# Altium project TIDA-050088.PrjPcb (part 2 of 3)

## Sheet TIDA-050088_LDOs.SchDoc
size 558 x 431 mm; Date: Not shown in title block; ApprovedBy: Not shown in title block; CheckedBy: Not shown in title block; Author: Not shown in title block; CompanyName: Not shown in title block; Engineer: Not shown in title block; Organization: Not shown in title block; Address1: Not shown in title block; Address2: Not shown in title block; Address3: Not shown in title block; Address4: Not shown in title block; DocumentNumber: 2; Revision: Use project parameter SCH_Rev; SheetNumber: 4; SheetTotal: 7; PageSetup: Record=PageOptions¦CenterHorizontal=True¦CenterVertical=True¦PrintScale=1.00¦XCorrection=1.00¦YCorrection=1.00¦PrintKind=0¦BorderSize=5000000¦LeftOffset=0¦BottomOffset=0¦Orientation=2¦PaperLength=1000¦PaperWidth=1000¦Scale=100¦PaperSource=15¦PrintQuality=600¦MediaType=1¦DitherType=10¦PaperKind=Letter¦PrintScaleMode=1
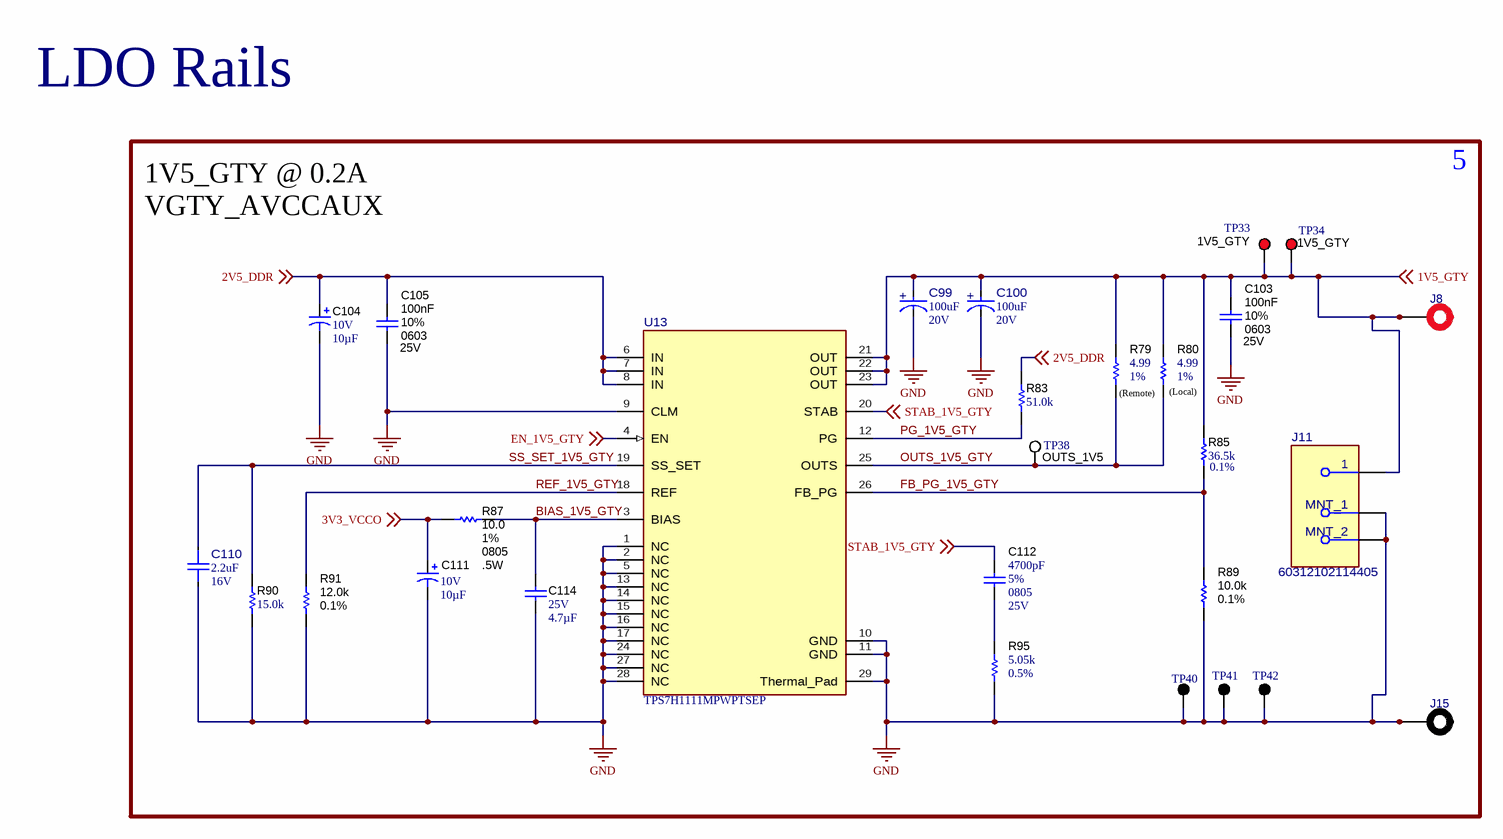
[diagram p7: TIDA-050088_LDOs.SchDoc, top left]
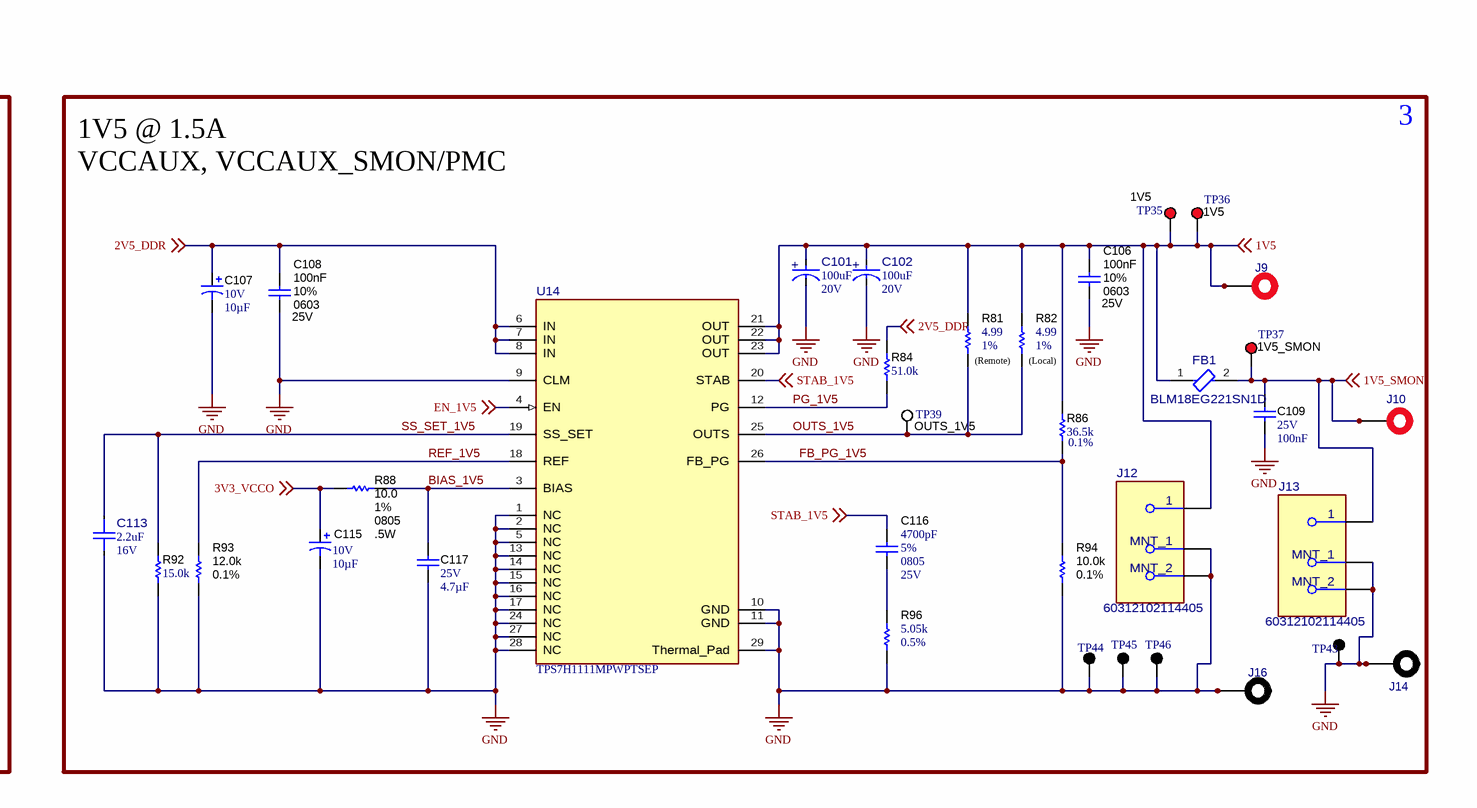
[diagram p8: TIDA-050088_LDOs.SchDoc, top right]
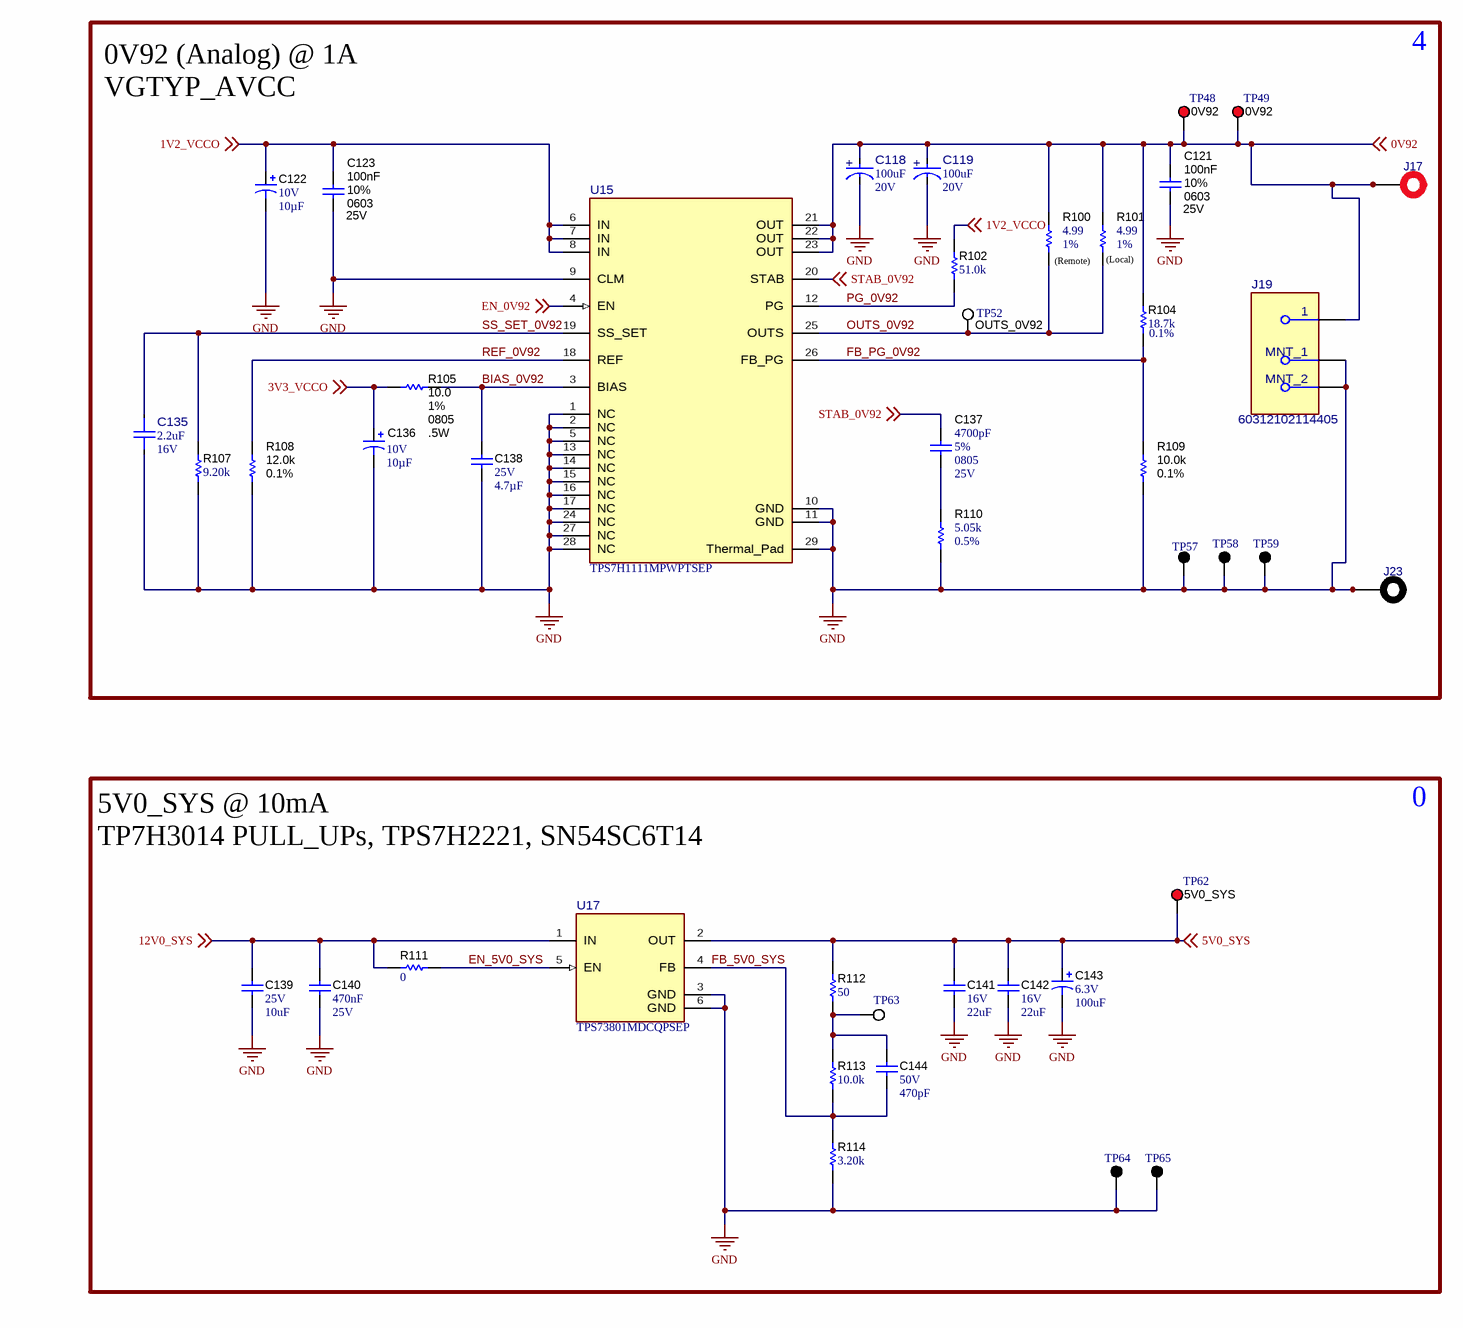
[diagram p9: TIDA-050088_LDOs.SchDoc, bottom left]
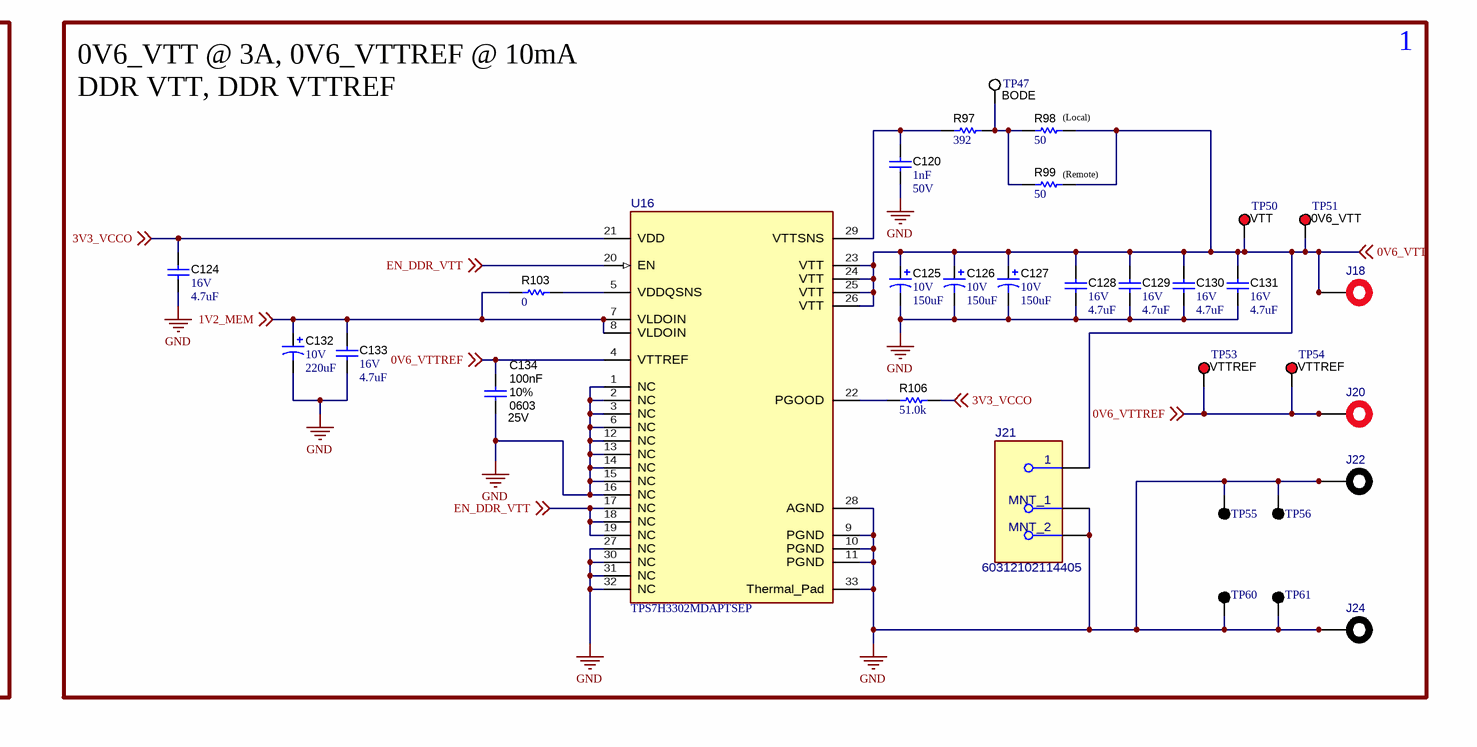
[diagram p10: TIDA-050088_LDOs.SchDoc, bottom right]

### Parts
C99  ValueDisplayed: 100uF  VDC_V: 20V  [FP-TRME107K020R0035_2917-MFG]  (hidden comment: TRME107K020R0035)
C100  ValueDisplayed: 100uF  VDC_V: 20V  [FP-TRME107K020R0035_2917-MFG]  (hidden comment: TRME107K020R0035)
C101  ValueDisplayed: 100uF  VDC_V: 20V  [FP-TRME107K020R0035_2917-MFG]  (hidden comment: TRME107K020R0035)
C102  ValueDisplayed: 100uF  VDC_V: 20V  [FP-TRME107K020R0035_2917-MFG]  (hidden comment: TRME107K020R0035)
C103  Tolerance_%: 10%  Cap_F: 100nF  VDC_V: 25V  [0603]  (hidden comment: C1608X7R1E104K080AA)
C104  VDC_V: 10V  ValueDisplayed: 10µF  [3216-18]  (hidden comment: T520A106M010ATE080)
C105  Tolerance_%: 10%  Cap_F: 100nF  VDC_V: 25V  [0603]  (hidden comment: 885012206071)
C106  Tolerance_%: 10%  Cap_F: 100nF  VDC_V: 25V  [0603]  (hidden comment: C1608X7R1E104K080AA)
C107  VDC_V: 10V  ValueDisplayed: 10µF  [3216-18]  (hidden comment: T520A106M010ATE080)
C108  Tolerance_%: 10%  Cap_F: 100nF  VDC_V: 25V  [0603]  (hidden comment: 885012206071)
C109  VDC_V: 25V  Cap_F: 100nF  [0603]  (hidden comment: GCM188R71E104KA57D)
C110  ValueDisplayed: 2.2uF  VDC_V: 16V  [FP-C1206C225K4RAC7800_1206-MFG]  (hidden comment: C1206C225K4RAC7800)
C111  VDC_V: 10V  ValueDisplayed: 10µF  [3216-18]  (hidden comment: T520A106M010ATE080)
C112  PackageReference: 0805  Tolerance_%: 5%  VDC_V: 25V  ValueDisplayed: 4700pF  [0805_HV]  (hidden comment: 08053A472JAT2A)
C113  ValueDisplayed: 2.2uF  VDC_V: 16V  [FP-C1206C225K4RAC7800_1206-MFG]  (hidden comment: C1206C225K4RAC7800)
C114  VDC_V: 25V  ValueDisplayed: 4.7µF  [1206_180]  (hidden comment: 12063C475KAT2A)
C115  VDC_V: 10V  ValueDisplayed: 10µF  [3216-18]  (hidden comment: T520A106M010ATE080)
C116  PackageReference: 0805  Tolerance_%: 5%  VDC_V: 25V  ValueDisplayed: 4700pF  [0805_HV]  (hidden comment: 08053A472JAT2A)
C117  VDC_V: 25V  ValueDisplayed: 4.7µF  [1206_180]  (hidden comment: 12063C475KAT2A)
C118  ValueDisplayed: 100uF  VDC_V: 20V  [FP-TRME107K020R0035_2917-MFG]  (hidden comment: TRME107K020R0035)
C119  ValueDisplayed: 100uF  VDC_V: 20V  [FP-TRME107K020R0035_2917-MFG]  (hidden comment: TRME107K020R0035)
C120  Cap_F: 1nF  VDC_V: 50V  [0603]  (hidden comment: C0603X102K5RACTU)
C121  Tolerance_%: 10%  Cap_F: 100nF  VDC_V: 25V  [0603]  (hidden comment: C1608X7R1E104K080AA)
C122  VDC_V: 10V  ValueDisplayed: 10µF  [3216-18]  (hidden comment: T520A106M010ATE080)
C123  Tolerance_%: 10%  Cap_F: 100nF  VDC_V: 25V  [0603]  (hidden comment: 885012206071)
C124  VDC_V: 16V  ValueDisplayed: 4.7uF  [1206_180]  (hidden comment: GCM31CR71C475KA37L)
C125  VDC_V: 10V  ValueDisplayed: 150uF  [7343-31]  (hidden comment: T530D157M010ATE005)
C126  VDC_V: 10V  ValueDisplayed: 150uF  [7343-31]  (hidden comment: T530D157M010ATE005)
C127  VDC_V: 10V  ValueDisplayed: 150uF  [7343-31]  (hidden comment: T530D157M010ATE005)
C128  VDC_V: 16V  ValueDisplayed: 4.7uF  [1206_180]  (hidden comment: GCM31CR71C475KA37L)
C129  VDC_V: 16V  ValueDisplayed: 4.7uF  [1206_180]  (hidden comment: GCM31CR71C475KA37L)
C130  VDC_V: 16V  ValueDisplayed: 4.7uF  [1206_180]  (hidden comment: GCM31CR71C475KA37L)
C131  VDC_V: 16V  ValueDisplayed: 4.7uF  [1206_180]  (hidden comment: GCM31CR71C475KA37L)
C132  VDC_V: 10V  ValueDisplayed: 220uF  [7343-31]  (hidden comment: T520D227M010ATE018)
C133  VDC_V: 16V  ValueDisplayed: 4.7uF  [1206_180]  (hidden comment: GCM31CR71C475KA37L)
C134  Tolerance_%: 10%  Cap_F: 100nF  VDC_V: 25V  [0603]  (hidden comment: C1608X7R1E104K080AA)
C135  ValueDisplayed: 2.2uF  VDC_V: 16V  [FP-C1206C225K4RAC7800_1206-MFG]  (hidden comment: C1206C225K4RAC7800)
C136  VDC_V: 10V  ValueDisplayed: 10µF  [3216-18]  (hidden comment: T520A106M010ATE080)
C137  PackageReference: 0805  Tolerance_%: 5%  VDC_V: 25V  ValueDisplayed: 4700pF  [0805_HV]  (hidden comment: 08053A472JAT2A)
C138  VDC_V: 25V  ValueDisplayed: 4.7µF  [1206_180]  (hidden comment: 12063C475KAT2A)
C139  VDC_V: 25V  ValueDisplayed: 10uF  [1210_220]  (hidden comment: 885012209028)
C140  Cap_F: 470nF  VDC_V: 25V  [0805_HV]  (hidden comment: CL21B474KAFNNNG)
C141  VDC_V: 16V  ValueDisplayed: 22uF  [1210_280]  (hidden comment: CGA6P1X7R1C226M250AC)
C142  VDC_V: 16V  ValueDisplayed: 22uF  [1210_280]  (hidden comment: CGA6P1X7R1C226M250AC)
C143  VDC_V: 6.3V  ValueDisplayed: 100uF  [3528-21]  (hidden comment: T520B107M006ATE015)
C144  VDC_V: 50V  ValueDisplayed: 470pF  [0603]  (hidden comment: GCM1885C1H471JA16D)
FB1  BLM18EG221SN1D  [FP-BLM18EG221SN1D_0603-MFG]
J8  571-0500  [571-0500]  (value not drawn)
J9  571-0500  [571-0500]  (value not drawn)
J10  571-0500  [571-0500]  (value not drawn)
J11  60312102114405  [FP-60312102114405_CONN_SMA-MFG]
J12  60312102114405  [FP-60312102114405_CONN_SMA-MFG]
J13  60312102114405  [FP-60312102114405_CONN_SMA-MFG]
J14  571-0100  [571-0100]  (value not drawn)
J15  571-0100  [571-0100]  (value not drawn)
J16  571-0100  [571-0100]  (value not drawn)
J17  571-0500  [571-0500]  (value not drawn)
J18  571-0500  [571-0500]  (value not drawn)
J19  60312102114405  [FP-60312102114405_CONN_SMA-MFG]
J20  571-0500  [571-0500]  (value not drawn)
J21  60312102114405  [FP-60312102114405_CONN_SMA-MFG]
J22  571-0100  [571-0100]  (value not drawn)
J23  571-0100  [571-0100]  (value not drawn)
J24  571-0100  [571-0100]  (value not drawn)
R79  Value1: 1%  ValueDisplayed: 4.99  [0603]  (hidden comment: RC0603FR-074R99L)
R80  Value1: 1%  ValueDisplayed: 4.99  [0603]  (hidden comment: RC0603FR-074R99L)
R81  Value1: 1%  ValueDisplayed: 4.99  [0603]  (hidden comment: RC0603FR-074R99L)
R82  Value1: 1%  ValueDisplayed: 4.99  [0603]  (hidden comment: RC0603FR-074R99L)
R83  ValueDisplayed: 51.0k  [0603]  (hidden comment: RC0603FR-0751KL)
R84  ValueDisplayed: 51.0k  [0603]  (hidden comment: RC0603FR-0751KL)
R85  Value1: 0.1%  ValueDisplayed: 36.5k  [0603]  (hidden comment: ERA-3AEB3652V)
R86  Value1: 0.1%  ValueDisplayed: 36.5k  [0603]  (hidden comment: ERA-3AEB3652V)
R87  Value1: 1%  PackageReference: 0805  Value2: .5W  ValueDisplayed: 10.0  [0805_HV]  (hidden comment: ERJ-P6WF10R0V)
R88  Value1: 1%  PackageReference: 0805  Value2: .5W  ValueDisplayed: 10.0  [0805_HV]  (hidden comment: ERJ-P6WF10R0V)
R89  Tolerance_%: 0.1%  ValueDisplayed: 10.0k  [0603]  (hidden comment: RT0603BRD0710KL)
R90  ValueDisplayed: 15.0k  [0603]  (hidden comment: RG1608P-153-B-T5)
R91  Value1: 0.1%  ValueDisplayed: 12.0k  [0603]  (hidden comment: RT0603BRD0712KL)
R92  ValueDisplayed: 15.0k  [0603]  (hidden comment: RG1608P-153-B-T5)
R93  Value1: 0.1%  ValueDisplayed: 12.0k  [0603]  (hidden comment: RT0603BRD0712KL)
R94  Tolerance_%: 0.1%  ValueDisplayed: 10.0k  [0603]  (hidden comment: RT0603BRD0710KL)
R95  Value1: 0.5%  ValueDisplayed: 5.05k  [0603]  (hidden comment: RT0603DRE075K05L)
R96  Value1: 0.5%  ValueDisplayed: 5.05k  [0603]  (hidden comment: RT0603DRE075K05L)
R97  ValueDisplayed: 392  [0603]  (hidden comment: RT0603BRD07392RL)
R98  ValueDisplayed: 50  [0603]  (hidden comment: FC0603E50R0BTBST1)
R99  ValueDisplayed: 50  [0603]  (hidden comment: FC0603E50R0BTBST1)
R100  Value1: 1%  ValueDisplayed: 4.99  [0603]  (hidden comment: RC0603FR-074R99L)
R101  Value1: 1%  ValueDisplayed: 4.99  [0603]  (hidden comment: RC0603FR-074R99L)
R102  ValueDisplayed: 51.0k  [0603]  (hidden comment: RC0603FR-0751KL)
R103  ValueDisplayed: 0  [0603]  (hidden comment: RCS06030000Z0EA)
R104  Value1: 0.1%  ValueDisplayed: 18.7k  [0603]  (hidden comment: ERA-3AEB1872V)
R105  Value1: 1%  PackageReference: 0805  Value2: .5W  ValueDisplayed: 10.0  [0805_HV]  (hidden comment: ERJ-P6WF10R0V)
R106  ValueDisplayed: 51.0k  [0603]  (hidden comment: RC0603FR-0751KL)
R107  ValueDisplayed: 9.20k  [0603]  (hidden comment: RT0603BRD079K2L)
R108  Value1: 0.1%  ValueDisplayed: 12.0k  [0603]  (hidden comment: RT0603BRD0712KL)
R109  Tolerance_%: 0.1%  ValueDisplayed: 10.0k  [0603]  (hidden comment: RT0603BRD0710KL)
R110  Value1: 0.5%  ValueDisplayed: 5.05k  [0603]  (hidden comment: RT0603DRE075K05L)
R111  ValueDisplayed: 0  [0603]  (hidden comment: RCS06030000Z0EA)
R112  ValueDisplayed: 50  [0603]  (hidden comment: FC0603E50R0BTBST1)
R113  ValueDisplayed: 10.0k  [0603]  (hidden comment: PHT0603Y1002BGT200)
R114  ValueDisplayed: 3.20k  [0603]  (hidden comment: RT0603BRD073K2L)
TP33  1V5_GTY  [Keystone5010]
TP34  1V5_GTY  [Keystone5010]
TP35  1V5  [Keystone5010]
TP36  1V5  [Keystone5010]
TP37  1V5_SMON  [Keystone5010]
TP38  OUTS_1V5  [Keystone5012]
TP39  OUTS_1V5  [Keystone5012]
TP40  GND  [Keystone5011]  (value not drawn)
TP41  GND  [Keystone5011]  (value not drawn)
TP42  GND  [Keystone5011]  (value not drawn)
TP43  GND  [Keystone5011]  (value not drawn)
TP44  GND  [Keystone5011]  (value not drawn)
TP45  GND  [Keystone5011]  (value not drawn)
TP46  GND  [Keystone5011]  (value not drawn)
TP47  BODE  [Keystone5012]
TP48  0V92  [Keystone5010]
TP49  0V92  [Keystone5010]
TP50  VTT  [Keystone5010]
TP51  0V6_VTT  [Keystone5010]
TP52  OUTS_0V92  [Keystone5012]
TP53  VTTREF  [Keystone5010]
TP54  VTTREF  [Keystone5010]
TP55  GND  [Keystone5011]  (value not drawn)
TP56  GND  [Keystone5011]  (value not drawn)
TP57  GND  [Keystone5011]  (value not drawn)
TP58  GND  [Keystone5011]  (value not drawn)
TP59  GND  [Keystone5011]  (value not drawn)
TP60  GND  [Keystone5011]  (value not drawn)
TP61  GND  [Keystone5011]  (value not drawn)
TP62  5V0_SYS  [Keystone5010]
TP63  BODE  [Keystone5012]  (value not drawn)
TP64  GND  [Keystone5011]  (value not drawn)
TP65  GND  [Keystone5011]  (value not drawn)
U13  TPS7H1111MPWPTSEP  [PWP0028A-MFG]
U14  TPS7H1111MPWPTSEP  [PWP0028A-MFG]
U15  TPS7H1111MPWPTSEP  [PWP0028A-MFG]
U16  TPS7H3302MDAPTSEP  [DAP0032F-MFG]
U17  TPS73801MDCQPSEP  [DCQ0006A-MFG]

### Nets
GND: C99.1(CATHODE) C100.1(CATHODE) C101.1(CATHODE) C102.1(CATHODE) C103.2 C104.2(-) C105.2 C106.2 C107.2(-) C108.2 C109.2 C110.2 C111.2(-) C113.2 C114.2 C115.2(-) C117.2 C118.1(CATHODE) C119.1(CATHODE) C120.2 C121.2 C122.2(-) C123.2 C124.2 C125.2(-) C126.2(-) C127.2(-) C128.2 C129.2 C130.2 C131.2 C132.2(-) C133.2 C134.2 C135.2 C136.2(-) C138.2 C139.2 C140.2 C141.2 C142.2 C143.2(-) J11.2(MNT_1) J11.3(MNT_2) J12.2(MNT_1) J12.3(MNT_2) J13.2(MNT_1) J13.3(MNT_2) J14.1 J14.2 J15.1 J15.2 J16.1 J16.2 J19.2(MNT_1) J19.3(MNT_2) J21.2(MNT_1) J21.3(MNT_2) J22.1 J22.2 J23.1 J23.2 J24.1 J24.2 R89.1 R90.1 R91.1 R92.1 R93.1 R94.1 R95.1 R96.1 R107.1 R108.1 R109.1 R110.1 R114.1 TP40.1 TP41.1 TP42.1 TP43.1 TP44.1 TP45.1 TP46.1 TP55.1 TP56.1 TP57.1 TP58.1 TP59.1 TP60.1 TP61.1 TP64.1 TP65.1 U13.1(NC) U13.2(NC) U13.5(NC) U13.9(CLM) U13.10(GND) U13.11(GND) U13.13(NC) U13.14(NC) U13.15(NC) U13.16(NC) U13.17(NC) U13.24(NC) U13.27(NC) U13.28(NC) U13.29(Thermal_Pad) U14.1(NC) U14.2(NC) U14.5(NC) U14.9(CLM) U14.10(GND) U14.11(GND) U14.13(NC) U14.14(NC) U14.15(NC) U14.16(NC) U14.17(NC) U14.24(NC) U14.27(NC) U14.28(NC) U14.29(Thermal_Pad) U15.1(NC) U15.2(NC) U15.5(NC) U15.9(CLM) U15.10(GND) U15.11(GND) U15.13(NC) U15.14(NC) U15.15(NC) U15.16(NC) U15.17(NC) U15.24(NC) U15.27(NC) U15.28(NC) U15.29(Thermal_Pad) U16.1(NC) U16.2(NC) U16.3(NC) U16.6(NC) U16.9(PGND) U16.10(PGND) U16.11(PGND) U16.12(NC) U16.13(NC) U16.14(NC) U16.15(NC) U16.16(NC) U16.27(NC) U16.28(AGND) U16.30(NC) U16.31(NC) U16.32(NC) U16.33(Thermal_Pad) U17.3(GND) U17.6(GND)
0V6_VTT: C125.1(+) C126.1(+) C127.1(+) C128.1 C129.1 C130.1 C131.1 J18.1 J18.2 J21.1 R98.1 R99.1 TP50.1 TP51.1 U16.23(VTT) U16.24(VTT) U16.25(VTT) U16.26(VTT) ; off-sheet 0V6_VTT
0V6_VTTREF: C134.1 J20.1 J20.2 TP53.1 TP54.1 U16.4(VTTREF) ; off-sheet 0V6_VTTREF
0V92: C118.2(ANODE) C119.2(ANODE) C121.1 J17.1 J17.2 J19.1 R100.2 R101.2 R104.2 TP48.1 TP49.1 U15.21(OUT) U15.22(OUT) U15.23(OUT) ; off-sheet 0V92
1V2_MEM: C132.1(+) C133.1 R103.1 U16.7(VLDOIN) U16.8(VLDOIN) ; off-sheet 1V2_MEM
1V2_VCCO: C122.1(+) C123.1 R102.2 U15.6(IN) U15.7(IN) U15.8(IN) ; off-sheet 1V2_VCCO
1V5: C101.2(ANODE) C102.2(ANODE) C106.1 FB1.1 J9.1 J9.2 J12.1 R81.2 R82.2 R86.2 TP35.1 TP36.1 U14.21(OUT) U14.22(OUT) U14.23(OUT) ; off-sheet 1V5
1V5_GTY: C99.2(ANODE) C100.2(ANODE) C103.1 J8.1 J8.2 J11.1 R79.2 R80.2 R85.2 TP33.1 TP34.1 U13.21(OUT) U13.22(OUT) U13.23(OUT) ; off-sheet 1V5_GTY
1V5_SMON: C109.1 FB1.2 J10.1 J10.2 J13.1 TP37.1 ; off-sheet 1V5_SMON
2V5_DDR: C104.1(+) C105.1 C107.1(+) C108.1 R83.2 R84.2 U13.6(IN) U13.7(IN) U13.8(IN) U14.6(IN) U14.7(IN) U14.8(IN) ; off-sheet 2V5_DDR
3V3_VCCO: C111.1(+) C115.1(+) C124.1 C136.1(+) R87.1 R88.1 R105.1 R106.2 U16.21(VDD) ; off-sheet 3V3_VCCO
5V0_SYS: C141.1 C142.1 C143.1(+) R112.2 TP62.1 U17.2(OUT) ; off-sheet 5V0_SYS
12V0_SYS: C139.1 C140.1 R111.1 U17.1(IN) ; off-sheet 12V0_SYS
BIAS_0V92: C138.1 R105.2 U15.3(BIAS)
BIAS_1V5: C117.1 R88.2 U14.3(BIAS)
BIAS_1V5_GTY: C114.1 R87.2 U13.3(BIAS)
EN_0V92: U15.4(EN) ; off-sheet EN_0V92
EN_1V5: U14.4(EN) ; off-sheet EN_1V5
EN_1V5_GTY: U13.4(EN) ; off-sheet EN_1V5_GTY
EN_5V0_SYS: R111.2 U17.5(EN)
EN_DDR_VTT: U16.17(NC) U16.18(NC) U16.19(NC) U16.20(EN) ; off-sheet EN_DDR_VTT
FB_5V0_SYS: C144.2 R113.1 R114.2 U17.4(FB)
FB_PG_0V92: R104.1 R109.2 U15.26(FB_PG)
FB_PG_1V5: R86.1 R94.2 U14.26(FB_PG)
FB_PG_1V5_GTY: R85.1 R89.2 U13.26(FB_PG)
OUTS_0V92: R100.1 R101.1 TP52.1 U15.25(OUTS)
OUTS_1V5: R81.1 R82.1 TP39.1 U14.25(OUTS)
OUTS_1V5_GTY: R79.1 R80.1 TP38.1 U13.25(OUTS)
PG_0V92: R102.1 U15.12(PG)
PG_1V5: R84.1 U14.12(PG)
PG_1V5_GTY: R83.1 U13.12(PG)
REF_0V92: R108.2 U15.18(REF)
REF_1V5: R93.2 U14.18(REF)
REF_1V5_GTY: R91.2 U13.18(REF)
SS_SET_0V92: C135.1 R107.2 U15.19(SS_SET)
SS_SET_1V5: C113.1 R92.2 U14.19(SS_SET)
SS_SET_1V5_GTY: C110.1 R90.2 U13.19(SS_SET)
STAB_0V92: C137.1 U15.20(STAB) ; off-sheet STAB_0V92
STAB_1V5: C116.1 U14.20(STAB) ; off-sheet STAB_1V5
STAB_1V5_GTY: C112.1 U13.20(STAB) ; off-sheet STAB_1V5_GTY
NetC112_2: C112.2 R95.2
NetC116_2: C116.2 R96.2
NetC120_1: C120.1 R97.1 U16.29(VTTSNS)
NetC137_2: C137.2 R110.2
NetC144_1: C144.1 R112.1 R113.2 TP63.1
NetR97_2: R97.2 R98.2 R99.2 TP47.1
NetR103_2: R103.2 U16.5(VDDQSNS)
NetR106_1: R106.1 U16.22(PGOOD)

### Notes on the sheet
- LDO Rails
- 1V5_GTY @ 0.2A
  VGTY_AVCCAUX
- 5
- 1V5 @ 1.5A
  VCCAUX, VCCAUX_SMON/PMC
- 3
- (Remote)
- (near R80) (Local)
- (near R82) (Local)
- 4
- 1
- 0V92 (Analog) @ 1A
  VGTYP_AVCC
- 0V6_VTT @ 3A, 0V6_VTTREF @ 10mA
  DDR VTT, DDR VTTREF
- (near R98) (Local)
- (near R99) (Remote)
- (near R101) (Local)
- 5V0_SYS @ 10mA
  TP7H3014 PULL_UPs, TPS7H2221, SN54SC6T14
- 0

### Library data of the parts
C99-C102 C118 C119 = CMP-0096895-1: Cap Tant Solid 100uF 20V E CASE 10% (7.3 X 4.1 X 4.3mm) SMD 7343-43 0.035 Ohm 125°C T/R; Manufacturer: KYOCERA AVX; Value: 100µF; AEC Qualified: No; Esr: 35m; Dissipation Factor: 6%; Life: 2000Hours; Leakage Current: 15uA; IRMS_A: 2.777A
C103 C106 C121 C134 = CMP-0007039-5: CAP, CERM, 0.1 uF, 25 V, +/- 10%, X7R, 0603; Manufacturer: TDK; TaMin_C: -55°C; Polarized: N; SizeAreaWB_mm2: 4.68; Value1: Unknown; U/M: EA; Value: 0.1uF; TaMax_C: 125°C; SizeZ_mm: 1; SizeX_mm: 1.6; SizeY_mm: 0.8; SizeArea_mm2: 1.28; AEC Category: Q200
C104 C107 C111 C115 C122 C136 = CMP-0084376-1: CAP, Tantalum Polymer, 10 µF, 10 V,+/- 20%, 0.08 ohm, 3216-18 SMD; Manufacturer: Kemet; TaMin_C: -55°C; SizeArea_mm2: 5.12; Value: 10uF; SizeAreaWB_mm2: 10.92; SizeY_mm: 1.6; Polarized: Y; SizeX_mm: 3.2; AEC Qualified: N; TaMax_C: 105°C; SizeZ_mm: 1.8; ESR_ohm: 80m; CompType: Capacitor; AEC Category: Q200
C105 C108 C123 = CMP-0006832-5: CAP, CERM, 0.1 uF, 25 V, +/- 10%, X7R, 0603; Manufacturer: Wurth Elektronik; TaMin_C: -55°C; Polarized: N; SizeAreaWB_mm2: 4.68; Value1: Unknown; U/M: EA; Value: 0.1uF; TaMax_C: 125°C; SizeZ_mm: 1; SizeX_mm: 1.6; SizeY_mm: 0.8; SizeArea_mm2: 1.28; AEC Category: Q200
C109 = CMP-0084679-1: CAP, CERM, 0.1 µF, 25 V,+/- 10%, X7R, AEC-Q200 Grade 1, 0603; Manufacturer: MuRata; TaMin_C: -55°C; SizeY_mm: 0.8; Polarized: N; SizeArea_mm2: 1.28; SizeZ_mm: 1; SizeX_mm: 1.6; AEC Qualified: Y; AEC Category: Q200; Value: 0.1uF; ValueDisplayed: 0.1µF; TaMax_C: 125°C; U/M: EA; SizeAreaWB_mm2: 4.68
C110 C113 C135 = CMP-0124122-1: 2.2 µF ±10% 16V Ceramic Capacitor X7R 1206 (3216 Metric); Manufacturer: KEMET; AEC Qualified: No; Cap_F: 2.2µF; SizeZ_mm: 1.8mm; TempCo: 15%; Value: 2.2µF
C112 C116 C137 = CMP-0007564-2: CAP, CERM, 4700 pF, 25 V, +/- 5%, C0G/NP0, 0805; Manufacturer: AVX; TaMin_C: -55°C; ESR_ohm: 0.556; Polarized: N; SizeAreaWB_mm2: 6.75; Value1: 0.556 ohm; U/M: EA; Value: 4700pF; TaMax_C: 125°C; SizeZ_mm: 1.45; SizeX_mm: 2; SizeY_mm: 1.25; SizeArea_mm2: 2.5; Cap_F: 4.7nF; AEC Category: Q200
C114 C117 C138 = CMP-0860521-1: CAP, CERM, 4.7 µF, 25 V,+/- 10%, X7R, 1206; Manufacturer: AVX; SizeAreaWB_mm2: 10.92; Cap_Case: 1206; TaMin_C: -55°C; SizeZ_mm: 1.8; AEC Category: Q200; U/M: EA; TaMax_C: 125°C; AEC Qualified: N; Value: 4.7uF; SizeY_mm: 1.6; SizeX_mm: 3.2; SizeArea_mm2: 5.12
C120 = CMP-0006976-5: CAP, CERM, 1000 pF, 50 V, +/- 10%, X7R, 0603; Manufacturer: Kemet; TaMin_C: -55°C; Polarized: N; SizeAreaWB_mm2: 4.68; Value1: Unknown; U/M: EA; Value: 1000pF; TaMax_C: 125°C; SizeZ_mm: 1; SizeX_mm: 1.6; SizeY_mm: 0.8; SizeArea_mm2: 1.28; AEC Category: Q200
C124 C128-C131 C133 = CMP-0008813-2: CAP, CERM, 4.7 uF, 16 V, +/- 10%, X7R, AEC-Q200 Grade 1, 1206; Manufacturer: MuRata; TaMin_C: -55°C; Polarized: N; SizeAreaWB_mm2: 10.92; Value1: Unknown; U/M: EA; Value: 4.7uF; TaMax_C: 125°C; SizeZ_mm: 1.8; SizeX_mm: 3.2; SizeY_mm: 1.6; Cap_Case: 1206; SizeArea_mm2: 5.12; AEC Qualified: Y; Cap_F: 4.7µF; AEC Grade: 1; AEC Category: Q200
C125-C127 = CMP-0012656-3: CAP, Tantalum Polymer, 150 uF, 10 V, +/- 20%, 0.005 ohm, 7343-31 SMD; Manufacturer: Kemet; TaMin_C: -55°C; ESR_ohm: 5m; Polarized: Y; SizeAreaWB_mm2: 58.59; Value: 150uF; TaMax_C: 125°C; SizeZ_mm: 3.1; SizeX_mm: 7.3; SizeY_mm: 4.3; Cap_Case: 7.3x4.3mm; SizeArea_mm2: 31.39; CompType: Capacitor; AEC Qualified: N; Cap_F: 150µF; AEC Category: Q200
C132 = CMP-0064985-2: CAP, Tantalum Polymer, 220 uF, 10 V,+/- 20%, 0.018 ohm, 7343-31 SMD; Manufacturer: Kemet; TaMin_C: -55°C; ESR_ohm: 18m; Polarized: Y; SizeAreaWB_mm2: 58.59; Value: 220uF; TaMax_C: 105°C; SizeZ_mm: 3.1; SizeX_mm: 7.3; SizeY_mm: 4.3; SizeArea_mm2: 31.39; CompType: Capacitor; AEC Qualified: N; Cap_F: 220µF; IRMS_A: 3.5A; AEC Category: Q200
C139 = CMP-0064938-2: CAP, CERM, 10 uF, 25 V,+/- 10%, X7R, 1210; Manufacturer: Wurth Elektronik; TaMin_C: -55°C; Polarized: N; SizeAreaWB_mm2: 14.7; Value1: Unknown; U/M: EA; Value: 10uF; TaMax_C: 125°C; SizeZ_mm: 2.2; SizeX_mm: 3.2; SizeY_mm: 2.5; Cap_Case: 1210; SizeArea_mm2: 8; Cap_F: 10µF; AEC Category: Q200
C140 = CMP-0007695-2: CAP CER 0.47UF 25V X7R 0805; Manufacturer: Samsung Electro-Mechanics; Tolerance_%: 10%; Cap_Case: 0805
C141 C142 = CMP-0009154-2: CAP, CERM, 22 uF, 16 V, +/- 20%, X7R, AEC-Q200 Grade 1, 1210; Manufacturer: TDK; TaMin_C: -55°C; ESR_ohm: 2.582m; Polarized: N; SizeAreaWB_mm2: 14.7; Value1: 0.002582 ohm; U/M: EA; Value: 22uF; TaMax_C: 125°C; SizeZ_mm: 2.8; SizeX_mm: 3.2; SizeY_mm: 2.5; SizeArea_mm2: 8; AEC Qualified: Y; Cap_F: 22µF; IRMS_A: 4.5756A; AEC Grade: 1; AEC Category: Q200
C143 = CMP-0011556-2: CAP, TA, 100 uF, 6.3 V, +/- 20%, 0.015 ohm, SMD; Manufacturer: Kemet; TaMin_C: -55°C; ESR_ohm: 15m; Polarized: Y; SizeAreaWB_mm2: 17.1; U/M: EA; Value: 100uF; TaMax_C: 105°C; SizeZ_mm: 2.1; SizeX_mm: 3.5; SizeY_mm: 2.8; SizeArea_mm2: 9.8; CompType: Capacitor; AEC Qualified: N; Cap_F: 100µF; IRMS_A: 2.9A; AEC Category: Q200
C144 = CMP-0007127-4: CAP, CERM, 470 pF, 50 V, +/- 5%, C0G/NP0, AEC-Q200 Grade 1, 0603; Manufacturer: MuRata; TaMin_C: -55°C; Polarized: N; SizeAreaWB_mm2: 4.68; Value1: Unknown; U/M: EA; Value: 470pF; TaMax_C: 125°C; SizeZ_mm: 1; SizeX_mm: 1.6; SizeY_mm: 0.8; SizeArea_mm2: 1.28; AEC Qualified: Y; AEC Category: Q200
FB1 = CMP-0122734-1: Chip Ferrite Bead, 0603, 220Ω @ 100MHz, 0.05Ω, 25%, 2A; Manufacturer: Murata; DCR_ohm: 50m; SizeZ_mm: 0.95mm; AEC Qualified: No
J8-J10 J17 J18 J20 = CMP-0055393-3: Standard Banana Jack, insulated, 10A, red; Manufacturer: DEM Manufacturing; Green_REACh: Incomplete; Green_Lifecycle: Not Set
J11-J13 J19 J21 = CMP-0098472-1: SMA Connector Jack, Female Socket 50Ohm Surface Mount Solder; Manufacturer: Wurth Electronics; ContactFinish: Gold,Nickel; Shrouded: true; AEC Qualified: No; Conn Orientation: Straight; Dielectric Material: PTFE; Frequency_Fixed: 0-18GHz; Impedance: 50Ω; Is Female: yes; SizeZ_mm: 9.04mm
J14-J16 J22-J24 = CMP-0055389-3: Standard Banana Jack, insulated, 10A, black; Manufacturer: DEM Manufacturing; Green_REACh: Incomplete; Green_Lifecycle: Not Set
R79-R82 R100 R101 = CMP-0023161-5: RES, 4.99, 1%, 0.1 W, 0603; Manufacturer: Yageo; Power_W: 100mW; TempCo: 200 ppm/C; Value_Code: 4R99; Value: 4.99; EIA_Code: E96; SizeX_mm: 1.6; SizeY_mm: 0.8; SizeZ_mm: 1; SizeArea_mm2: 1.28; AEC Qualified: N; AEC Category: Q200; SizeAreaWB_mm2: 4.68
R83 R84 R102 R106 = CMP-0023167-5: RES, 51.0 k, 1%, 0.1 W, 0603; Manufacturer: Yageo; Power_W: 100mW; TempCo: 100 ppm/C; Value_Code: 51k0; Value: 51.0k; Res_ohm: 51k; SizeX_mm: 1.6; SizeY_mm: 0.8; SizeZ_mm: 1; Value2: 0.1W; SizeArea_mm2: 1.28; AEC Qualified: N; VDC_V: 75V; AEC Category: Q200; SizeAreaWB_mm2: 4.68
R85 R86 = CMP-0024147-3: RES SMD 36.5KOHM 0.1% 1/10W 0603; Manufacturer: Panasonic Electronic Components; Value_Code: 36k5; Value: 36.5k
R87 R88 R105 = CMP-0065342-2: RES, 10.0, 1%, .5 W, AEC-Q200 Grade 0, 0805; Manufacturer: Panasonic; Power_W: 500mW; TempCo: 200 ppm/C; Value_Code: 10R0; U/M: EA; Value: 10.0; EIA_Code: E96; Res_ohm: 10; SizeX_mm: 2.0; SizeY_mm: 1.25; SizeZ_mm: 1.45; SizeArea_mm2: 2.5; AEC Qualified: Y; AEC Grade: 0; AEC Category: Q200
R89 R94 R109 = CMP-0023653-3: RES, 10.0 k, 0.1%, 0.1 W, 0603; Manufacturer: Yageo America; Power_W: 100mW; TempCo: 25 ppm/C; Value_Code: 10k0; U/M: EA; Value: 10.0k; EIA_Code: E192; Res_ohm: 10k; SizeX_mm: 1.6; SizeY_mm: 0.8; SizeZ_mm: 1; SizeArea_mm2: 1.28; AEC Category: Q200
R90 R92 = CMP-0023441-3: RES, 15.0 k, 0.1%, 0.1 W, 0603; Manufacturer: Susumu Co Ltd; Power_W: 100mW; TempCo: 25 ppm/C; Value_Code: 15k0; U/M: EA; Value: 15.0k; EIA_Code: E192; Res_ohm: 15k; SizeX_mm: 1.6; SizeY_mm: 0.8; SizeZ_mm: 1; Value2: 0.1W; SizeArea_mm2: 1.28; VDC_V: 75V; AEC Category: Q200
R91 R93 R108 = CMP-0023710-3: RES, 12.0 k, 0.1%, 0.1 W, 0603; Manufacturer: Yageo America; Power_W: 100mW; TempCo: 25 ppm/C; Value_Code: 12k0; U/M: EA; Value: 12.0k; EIA_Code: E192; Res_ohm: 12k; SizeX_mm: 1.6; SizeY_mm: 0.8; SizeZ_mm: 1; SizeArea_mm2: 1.28; VDC_V: 75V; AEC Category: Q200
R95 R96 R110 = CMP-0025433-3: RES, 5.05 k, 0.5%, 0.1 W, 0603; Manufacturer: Yageo America; TempCo: 50 ppm/C; Value_Code: 5k05; U/M: EA; Value: 5.05k; EIA_Code: E192; SizeX_mm: 1.6; SizeY_mm: 0.8; SizeZ_mm: 1; Value2: 0.1W; SizeArea_mm2: 1.28; AEC Category: Q200
R97 = CMP-0024179-2: RES, 392, 0.1%, 0.1 W, 0603; Manufacturer: Yageo America; TempCo: 25 ppm/C; Value_Code: 392R; U/M: EA; Value: 392; EIA_Code: E192; SizeX_mm: 1.6; SizeY_mm: 0.8; SizeZ_mm: 1; Value2: 0.1W; SizeArea_mm2: 1.28; Power_W: 100mW; VDC_V: 75V; AEC Category: Q200
R98 R99 R112 = CMP-0023387-3: RES, 50, 0.1%, 0.125 W, 0603; Manufacturer: Vishay Thin Film; Power_W: 125mW; TempCo: 25 ppm/C; Value_Code: 50R0; U/M: EA; Value: 50; SizeX_mm: 1.6; SizeY_mm: 0.8; SizeZ_mm: 1; Value2: 0.125W; SizeArea_mm2: 1.28; AEC Qualified: N; VDC_V: 50V; AEC Category: Q200
R103 R111 = CMP-0081973-1: RES, 0, 0%, 0.25 W, AEC-Q200 Grade 0, 0603; Manufacturer: Vishay-Dale; SizeAreaWB_mm2: 4.68; SizeArea_mm2: 1.28; AEC Qualified: Y; AEC Category: Q200; Value: 0; SizeZ_mm: 1; SizeY_mm: 0.8; Power_W: 250mW; Value2: 0.25W; SizeX_mm: 1.6
R104 = CMP-0023840-3: RES SMD 18.7KOHM 0.1% 1/10W 0603; Manufacturer: Panasonic Electronic Components; Value_Code: 18k7; Value: 18.7k
R107 = CMP-0024552-2: RES, 9.20 k, 0.1%, 0.1 W, 0603; Manufacturer: Yageo America; Power_W: 100mW; TempCo: 25 ppm/C; Value_Code: 9k20; U/M: EA; Value: 9.20k; EIA_Code: E192; Res_ohm: 9.2k; SizeX_mm: 1.6; SizeY_mm: 0.8; SizeZ_mm: 1; Value2: 0.1W; SizeArea_mm2: 1.28; VDC_V: 75V; AEC Category: Q200
R113 = CMP-0023392-3: RES, 10.0 k, 0.1%, 0.0375 W, 0603; Manufacturer: Vishay Sfernice; Power_W: 37.5mW; TempCo: 15 ppm/C; Value_Code: 10k0; U/M: EA; Value: 10.0k; EIA_Code: E192; Res_ohm: 10k; SizeX_mm: 1.6; SizeY_mm: 0.8; SizeZ_mm: 1; SizeArea_mm2: 1.28; VDC_V: 75V; AEC Category: Q200
R114 = CMP-0024193-2: RES, 3.20 k, 0.1%, 0.1 W, 0603; Manufacturer: Yageo America; Power_W: 100mW; TempCo: 25 ppm/C; Value_Code: 3k20; U/M: EA; Value: 3.20k; EIA_Code: E192; Res_ohm: 3.2k; SizeX_mm: 1.6; SizeY_mm: 0.8; SizeZ_mm: 1; Value2: 0.1W; SizeArea_mm2: 1.28; VDC_V: 75V; AEC Category: Q200
TP33-TP37 TP48-TP51 TP53 TP54 TP62 = CMP-0055147-2: Test Point, Multipurpose, Red, TH; Manufacturer: Keystone Electronics; CT: TRUE; ContactFinish: Silver; Green_Lifecycle: Active; CNHeader: FALSE; Green_REACh: Passed
TP38 TP39 TP47 TP52 TP63 = CMP-0055149-2: Test Point, Multipurpose, White, TH; Manufacturer: Keystone Electronics; ContactFinish: Silver; CT: TRUE; CNHeader: FALSE; Green_Lifecycle: Active; Green_REACh: Passed
TP40-TP46 TP55-TP61 TP64 TP65 = CMP-0055148-2: Test Point, Multipurpose, Black, TH; Manufacturer: Keystone Electronics; CNHeader: FALSE; Green_Lifecycle: Active; Green_REACh: Passed; ContactFinish: Silver; CT: TRUE
U13-U15 = CMP-0096731-1: 1.5-A, Ultra-Low Noise, High PSRR Radiation Hardened LDO; Manufacturer: Texas Instruments; Standoff Height: 0.02mm; Max Supply Voltage: 7V; Output Type: AdjustableProgrammable; TJmax_C: +125°C; Accuracy Percentage: 0.6%; AEC Qualified: No; Nominal Supply Current: 19mA; Output Voltage: 0.4-5.5V; Min Supply Voltage: 850mV; Dropout Voltage: 1168mV; SizeZ_mm: 1.1mm; Number Of Outputs: 1
U16 = CMP-0095960-3: Radiation-Tolerant 3-A DDR Termination Regulator, HTSSOP32; Manufacturer: Texas Instruments; AEC Category: Q200; Max Supply Voltage: 3.5V; TJmax_C: +125°C; Output Voltage: 0.5-1.75V; CompType: IC; Min Supply Voltage: 900mV; Standoff Height: 0.05mm; Number Of Outputs: 2; AEC Qualified: No; SizeZ_mm: 1.2mm
U17 = CMP-0094005-1: LDO Regulator Pos 1.21V to 20V 1A 6-Pin(5+Tab) SOT-223 Tube; Manufacturer: Texas Instruments; TJmax_C: +125°C; Output Voltage: 1.21-20V; AEC Qualified: No; Nominal Supply Current: 1-35mA; SizeZ_mm: 1.8mm; Standoff Height: 0.02mm; Min Supply Voltage: 1.45V; Output Type: AdjustableProgrammable; Number Of Outputs: 1; Dropout Voltage: 0.24V

## Sheet TIDA-050088_Bucks.SchDoc
size 558 x 431 mm; Date: Not shown in title block; ApprovedBy: Not shown in title block; CheckedBy: Not shown in title block; Author: Not shown in title block; CompanyName: Not shown in title block; Engineer: Not shown in title block; Organization: Not shown in title block; Address1: Not shown in title block; Address2: Not shown in title block; Address3: Not shown in title block; Address4: Not shown in title block; DocumentNumber: 2; Revision: Use project parameter SCH_Rev; SheetNumber: 5; SheetTotal: 7; PageSetup: Record=PageOptions¦CenterHorizontal=True¦CenterVertical=True¦PrintScale=1.00¦XCorrection=1.00¦YCorrection=1.00¦PrintKind=0¦BorderSize=5000000¦LeftOffset=0¦BottomOffset=0¦Orientation=2¦PaperLength=1000¦PaperWidth=1000¦Scale=100¦PaperSource=15¦PrintQuality=600¦MediaType=1¦DitherType=10¦PaperKind=Letter¦PrintScaleMode=1
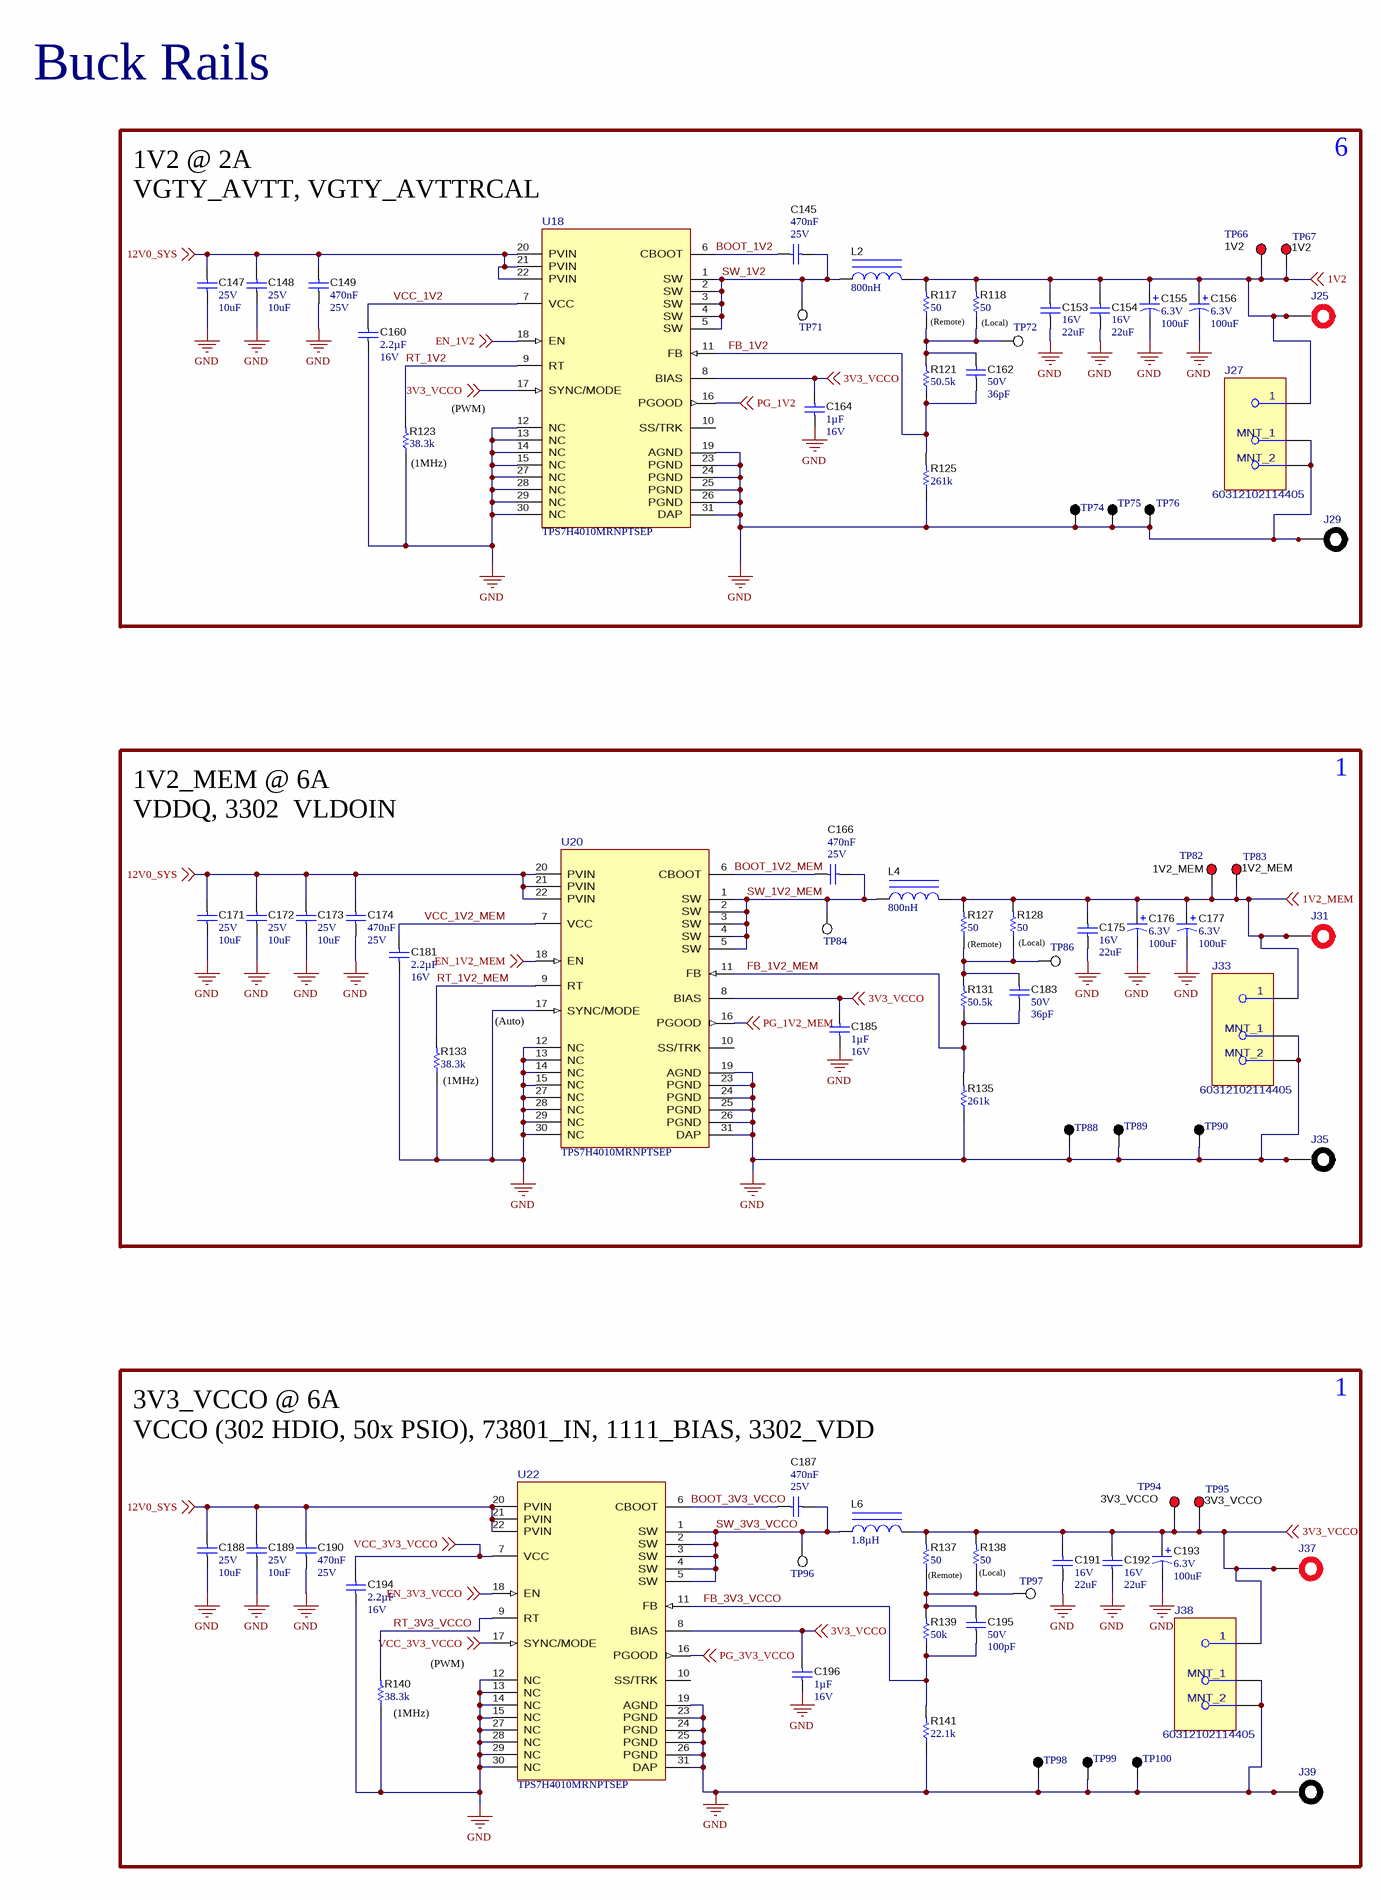
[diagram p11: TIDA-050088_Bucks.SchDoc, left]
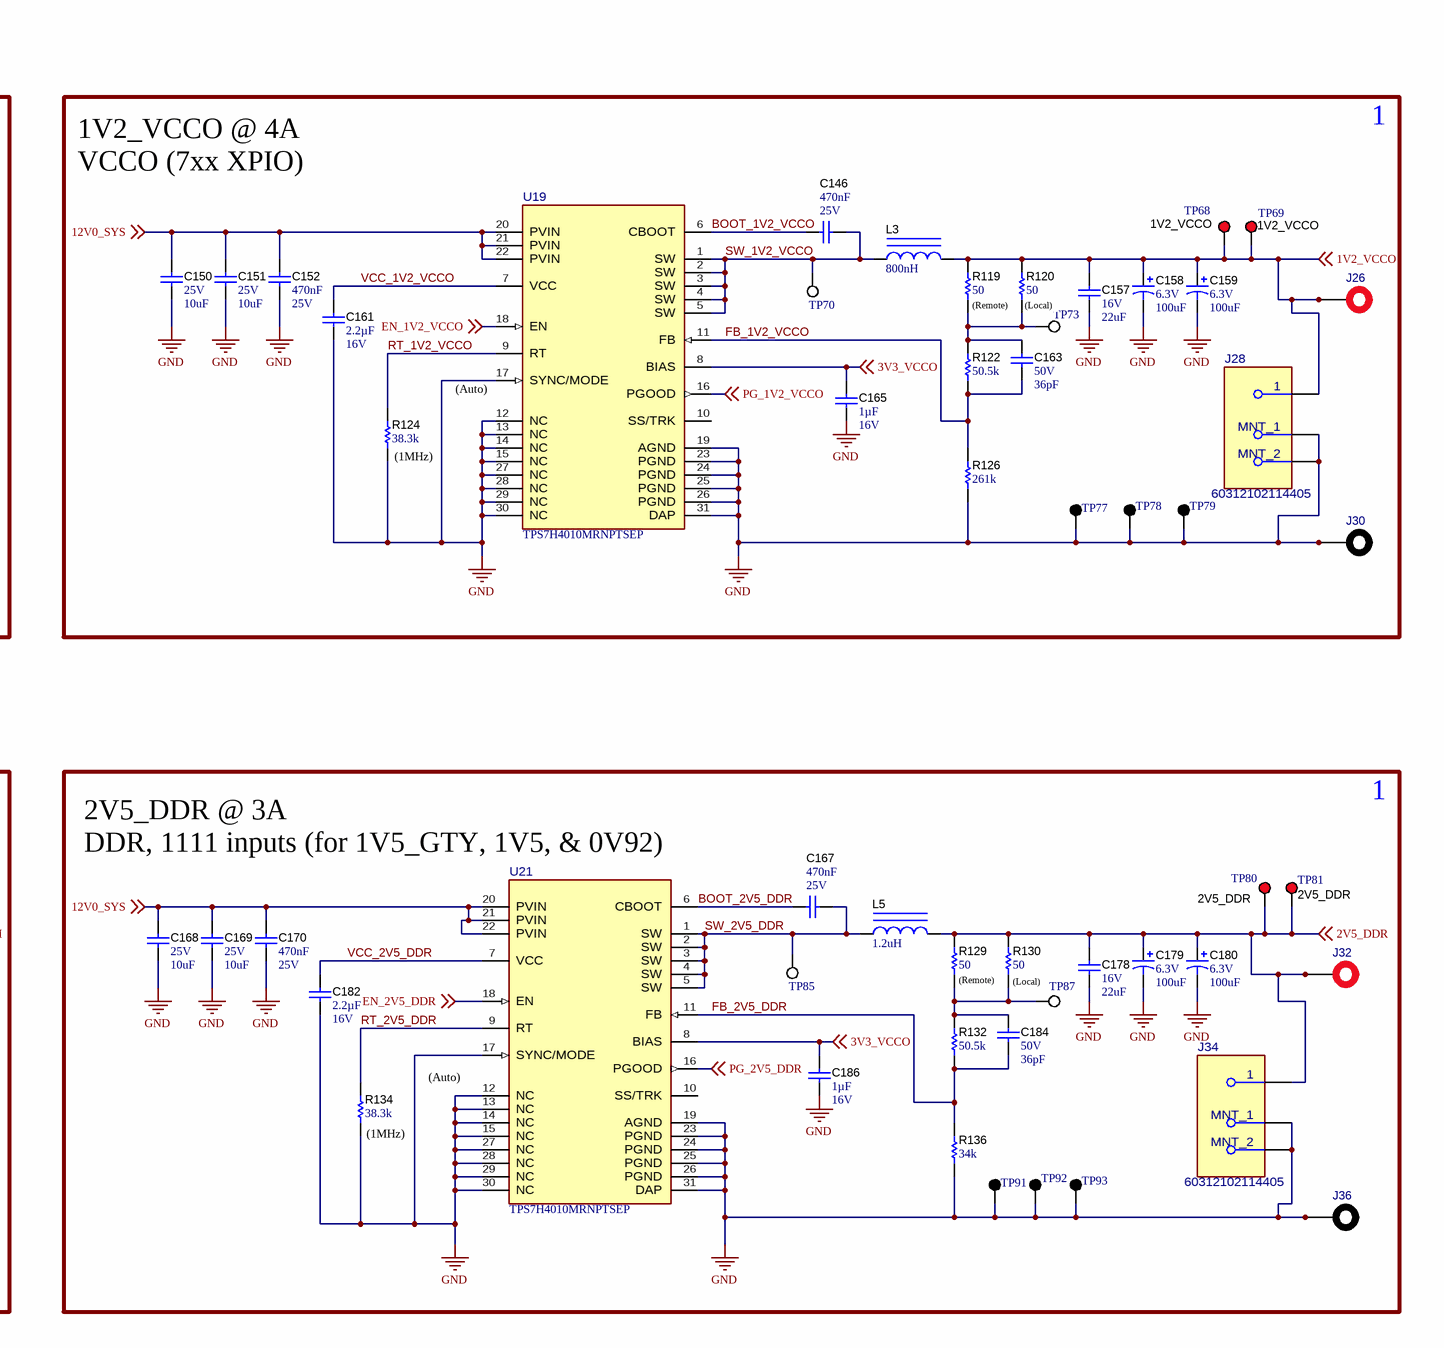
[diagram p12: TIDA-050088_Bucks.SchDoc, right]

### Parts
C145  Cap_F: 470nF  VDC_V: 25V  [0805_HV]  (hidden comment: CL21B474KAFNNNG)
C146  Cap_F: 470nF  VDC_V: 25V  [0805_HV]  (hidden comment: CL21B474KAFNNNG)
C147  VDC_V: 25V  ValueDisplayed: 10uF  [1210_220]  (hidden comment: 885012209028)
C148  VDC_V: 25V  ValueDisplayed: 10uF  [1210_220]  (hidden comment: 885012209028)
C149  Cap_F: 470nF  VDC_V: 25V  [0805_HV]  (hidden comment: C0805C474K3RACAUTO)
C150  VDC_V: 25V  ValueDisplayed: 10uF  [1210_220]  (hidden comment: 885012209028)
C151  VDC_V: 25V  ValueDisplayed: 10uF  [1210_220]  (hidden comment: 885012209028)
C152  Cap_F: 470nF  VDC_V: 25V  [0805_HV]  (hidden comment: C0805C474K3RACAUTO)
C153  VDC_V: 16V  ValueDisplayed: 22uF  [1210_280]  (hidden comment: CGA6P1X7R1C226M250AC)
C154  VDC_V: 16V  ValueDisplayed: 22uF  [1210_280]  (hidden comment: CGA6P1X7R1C226M250AC)
C155  VDC_V: 6.3V  ValueDisplayed: 100uF  [3528-21]  (hidden comment: T520B107M006ATE015)
C156  VDC_V: 6.3V  ValueDisplayed: 100uF  [3528-21]  (hidden comment: T520B107M006ATE015)
C157  VDC_V: 16V  ValueDisplayed: 22uF  [1210_280]  (hidden comment: CGA6P1X7R1C226M250AC)
C158  VDC_V: 6.3V  ValueDisplayed: 100uF  [3528-21]  (hidden comment: T520B107M006ATE015)
C159  VDC_V: 6.3V  ValueDisplayed: 100uF  [3528-21]  (hidden comment: T520B107M006ATE015)
C160  Cap_F: 2.2µF  VDC_V: 16V  [0805_HV]  (hidden comment: C2012X7R1C225K125AB)
C161  Cap_F: 2.2µF  VDC_V: 16V  [0805_HV]  (hidden comment: C2012X7R1C225K125AB)
C162  VDC_V: 50V  ValueDisplayed: 36pF  [0603]  (hidden comment: GRM1885C1H360JA01D)
C163  VDC_V: 50V  ValueDisplayed: 36pF  [0603]  (hidden comment: GRM1885C1H360JA01D)
C164  Cap_F: 1µF  VDC_V: 16V  [0805_HV]  (hidden comment: C0805C105K4RACTU)
C165  Cap_F: 1µF  VDC_V: 16V  [0805_HV]  (hidden comment: C0805C105K4RACTU)
C166  Cap_F: 470nF  VDC_V: 25V  [0805_HV]  (hidden comment: CL21B474KAFNNNG)
C167  Cap_F: 470nF  VDC_V: 25V  [0805_HV]  (hidden comment: CL21B474KAFNNNG)
C168  VDC_V: 25V  ValueDisplayed: 10uF  [1210_220]  (hidden comment: 885012209028)
C169  VDC_V: 25V  ValueDisplayed: 10uF  [1210_220]  (hidden comment: 885012209028)
C170  Cap_F: 470nF  VDC_V: 25V  [0805_HV]  (hidden comment: C0805C474K3RACAUTO)
C171  VDC_V: 25V  ValueDisplayed: 10uF  [1210_220]  (hidden comment: 885012209028)
C172  VDC_V: 25V  ValueDisplayed: 10uF  [1210_220]  (hidden comment: 885012209028)
C173  VDC_V: 25V  ValueDisplayed: 10uF  [1210_220]  (hidden comment: 885012209028)
C174  Cap_F: 470nF  VDC_V: 25V  [0805_HV]  (hidden comment: C0805C474K3RACAUTO)
C175  VDC_V: 16V  ValueDisplayed: 22uF  [1210_280]  (hidden comment: CGA6P1X7R1C226M250AC)
C176  VDC_V: 6.3V  ValueDisplayed: 100uF  [3528-21]  (hidden comment: T520B107M006ATE015)
C177  VDC_V: 6.3V  ValueDisplayed: 100uF  [3528-21]  (hidden comment: T520B107M006ATE015)
C178  VDC_V: 16V  ValueDisplayed: 22uF  [1210_280]  (hidden comment: CGA6P1X7R1C226M250AC)
C179  VDC_V: 6.3V  ValueDisplayed: 100uF  [3528-21]  (hidden comment: T520B107M006ATE015)
C180  VDC_V: 6.3V  ValueDisplayed: 100uF  [3528-21]  (hidden comment: T520B107M006ATE015)
C181  Cap_F: 2.2µF  VDC_V: 16V  [0805_HV]  (hidden comment: C2012X7R1C225K125AB)
C182  Cap_F: 2.2µF  VDC_V: 16V  [0805_HV]  (hidden comment: C2012X7R1C225K125AB)
C183  VDC_V: 50V  ValueDisplayed: 36pF  [0603]  (hidden comment: GRM1885C1H360JA01D)
C184  VDC_V: 50V  ValueDisplayed: 36pF  [0603]  (hidden comment: GRM1885C1H360JA01D)
C185  Cap_F: 1µF  VDC_V: 16V  [0805_HV]  (hidden comment: C0805C105K4RACTU)
C186  Cap_F: 1µF  VDC_V: 16V  [0805_HV]  (hidden comment: C0805C105K4RACTU)
C187  Cap_F: 470nF  VDC_V: 25V  [0805_HV]  (hidden comment: CL21B474KAFNNNG)
C188  VDC_V: 25V  ValueDisplayed: 10uF  [1210_220]  (hidden comment: 885012209028)
C189  VDC_V: 25V  ValueDisplayed: 10uF  [1210_220]  (hidden comment: 885012209028)
C190  Cap_F: 470nF  VDC_V: 25V  [0805_HV]  (hidden comment: C0805C474K3RACAUTO)
C191  VDC_V: 16V  ValueDisplayed: 22uF  [1210_280]  (hidden comment: CGA6P1X7R1C226M250AC)
C192  VDC_V: 16V  ValueDisplayed: 22uF  [1210_280]  (hidden comment: CGA6P1X7R1C226M250AC)
C193  VDC_V: 6.3V  ValueDisplayed: 100uF  [3528-21]  (hidden comment: T520B107M006ATE015)
C194  Cap_F: 2.2µF  VDC_V: 16V  [0805_HV]  (hidden comment: C2012X7R1C225K125AB)
C195  VDC_V: 50V  ValueDisplayed: 100pF  [0603]  (hidden comment: GRM1885C1H101JA01D)
C196  Cap_F: 1µF  VDC_V: 16V  [0805_HV]  (hidden comment: C0805C105K4RACTU)
J25  571-0500  [571-0500]  (value not drawn)
J26  571-0500  [571-0500]  (value not drawn)
J27  60312102114405  [FP-60312102114405_CONN_SMA-MFG]
J28  60312102114405  [FP-60312102114405_CONN_SMA-MFG]
J29  571-0100  [571-0100]  (value not drawn)
J30  571-0100  [571-0100]  (value not drawn)
J31  571-0500  [571-0500]  (value not drawn)
J32  571-0500  [571-0500]  (value not drawn)
J33  60312102114405  [FP-60312102114405_CONN_SMA-MFG]
J34  60312102114405  [FP-60312102114405_CONN_SMA-MFG]
J35  571-0100  [571-0100]  (value not drawn)
J36  571-0100  [571-0100]  (value not drawn)
J37  571-0500  [571-0500]  (value not drawn)
J38  60312102114405  [FP-60312102114405_CONN_SMA-MFG]
J39  571-0100  [571-0100]  (value not drawn)
L2  ValueDisplayed: 800nH  [XAL5030]  (hidden comment: XAL5030-801MEB)
L3  ValueDisplayed: 800nH  [XAL5030]  (hidden comment: XAL5030-801MEB)
L4  ValueDisplayed: 800nH  [XAL5030]  (hidden comment: XAL5030-801MEB)
L5  ValueDisplayed: 1.2uH  [XAL5030]  (hidden comment: XAL5030-122MEB)
L6  ValueDisplayed: 1.8µH  [XAL6030]  (hidden comment: XAL6030-182MEB)
R117  ValueDisplayed: 50  [0603]  (hidden comment: FC0603E50R0BTBST1)
R118  ValueDisplayed: 50  [0603]  (hidden comment: FC0603E50R0BTBST1)
R119  ValueDisplayed: 50  [0603]  (hidden comment: FC0603E50R0BTBST1)
R120  ValueDisplayed: 50  [0603]  (hidden comment: FC0603E50R0BTBST1)
R121  ValueDisplayed: 50.5k  [0603]  (hidden comment: TNPW060350K5BEEA)
R122  ValueDisplayed: 50.5k  [0603]  (hidden comment: TNPW060350K5BEEA)
R123  ValueDisplayed: 38.3k  [0603]  (hidden comment: CRCW060338K3FKEA)
R124  ValueDisplayed: 38.3k  [0603]  (hidden comment: CRCW060338K3FKEA)
R125  ValueDisplayed: 261k  [0603]  (hidden comment: ERA-3AEB2613V)
R126  ValueDisplayed: 261k  [0603]  (hidden comment: ERA-3AEB2613V)
R127  ValueDisplayed: 50  [0603]  (hidden comment: FC0603E50R0BTBST1)
R128  ValueDisplayed: 50  [0603]  (hidden comment: FC0603E50R0BTBST1)
R129  ValueDisplayed: 50  [0603]  (hidden comment: FC0603E50R0BTBST1)
R130  ValueDisplayed: 50  [0603]  (hidden comment: FC0603E50R0BTBST1)
R131  ValueDisplayed: 50.5k  [0603]  (hidden comment: TNPW060350K5BEEA)
R132  ValueDisplayed: 50.5k  [0603]  (hidden comment: TNPW060350K5BEEA)
R133  ValueDisplayed: 38.3k  [0603]  (hidden comment: CRCW060338K3FKEA)
R134  ValueDisplayed: 38.3k  [0603]  (hidden comment: CRCW060338K3FKEA)
R135  ValueDisplayed: 261k  [0603]  (hidden comment: ERA-3AEB2613V)
R136  ValueDisplayed: 34k  [0603]  (hidden comment: RN73H1JTTD3402B25)
R137  ValueDisplayed: 50  [0603]  (hidden comment: FC0603E50R0BTBST1)
R138  ValueDisplayed: 50  [0603]  (hidden comment: FC0603E50R0BTBST1)
R139  ValueDisplayed: 50k  [0603]  (hidden comment: RT0603BRD0750KL)
R140  ValueDisplayed: 38.3k  [0603]  (hidden comment: CRCW060338K3FKEA)
R141  ValueDisplayed: 22.1k  [0603]  (hidden comment: RT0603BRD0722K1L)
TP66  1V2  [Keystone5010]
TP67  1V2  [Keystone5010]
TP68  1V2_VCCO  [Keystone5010]
TP69  1V2_VCCO  [Keystone5010]
TP70  SW  [Keystone5012]  (value not drawn)
TP71  SW  [Keystone5012]  (value not drawn)
TP72  BODE  [Keystone5012]  (value not drawn)
TP73  BODE  [Keystone5012]  (value not drawn)
TP74  GND  [Keystone5011]  (value not drawn)
TP75  GND  [Keystone5011]  (value not drawn)
TP76  GND  [Keystone5011]  (value not drawn)
TP77  GND  [Keystone5011]  (value not drawn)
TP78  GND  [Keystone5011]  (value not drawn)
TP79  GND  [Keystone5011]  (value not drawn)
TP80  2V5_DDR  [Keystone5010]
TP81  2V5_DDR  [Keystone5010]
TP82  1V2_MEM  [Keystone5010]
TP83  1V2_MEM  [Keystone5010]
TP84  SW  [Keystone5012]  (value not drawn)
TP85  SW  [Keystone5012]  (value not drawn)
TP86  BODE  [Keystone5012]  (value not drawn)
TP87  BODE  [Keystone5012]  (value not drawn)
TP88  GND  [Keystone5011]  (value not drawn)
TP89  GND  [Keystone5011]  (value not drawn)
TP90  GND  [Keystone5011]  (value not drawn)
TP91  GND  [Keystone5011]  (value not drawn)
TP92  GND  [Keystone5011]  (value not drawn)
TP93  GND  [Keystone5011]  (value not drawn)
TP94  3V3_VCCO  [Keystone5010]
TP95  3V3_VCCO  [Keystone5010]
TP96  SW  [Keystone5012]  (value not drawn)
TP97  BODE  [Keystone5012]  (value not drawn)
TP98  GND  [Keystone5011]  (value not drawn)
TP99  GND  [Keystone5011]  (value not drawn)
TP100  GND  [Keystone5011]  (value not drawn)
U18  TPS7H4010MRNPTSEP  [RNP0030A-MFG]
U19  TPS7H4010MRNPTSEP  [RNP0030A-MFG]
U20  TPS7H4010MRNPTSEP  [RNP0030A-MFG]
U21  TPS7H4010MRNPTSEP  [RNP0030A-MFG]
U22  TPS7H4010MRNPTSEP  [RNP0030A-MFG]

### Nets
GND: C147.2 C148.2 C149.2 C150.2 C151.2 C152.2 C153.2 C154.2 C155.2(-) C156.2(-) C157.2 C158.2(-) C159.2(-) C160.2 C161.2 C164.2 C165.2 C168.2 C169.2 C170.2 C171.2 C172.2 C173.2 C174.2 C175.2 C176.2(-) C177.2(-) C178.2 C179.2(-) C180.2(-) C181.2 C182.2 C185.2 C186.2 C188.2 C189.2 C190.2 C191.2 C192.2 C193.2(-) C194.2 C196.2 J27.2(MNT_1) J27.3(MNT_2) J28.2(MNT_1) J28.3(MNT_2) J29.1 J29.2 J30.1 J30.2 J33.2(MNT_1) J33.3(MNT_2) J34.2(MNT_1) J34.3(MNT_2) J35.1 J35.2 J36.1 J36.2 J38.2(MNT_1) J38.3(MNT_2) J39.1 J39.2 R123.1 R124.1 R125.1 R126.1 R133.1 R134.1 R135.1 R136.1 R140.1 R141.1 TP74.1 TP75.1 TP76.1 TP77.1 TP78.1 TP79.1 TP88.1 TP89.1 TP90.1 TP91.1 TP92.1 TP93.1 TP98.1 TP99.1 TP100.1 U18.12(NC) U18.13(NC) U18.14(NC) U18.15(NC) U18.19(AGND) U18.23(PGND) U18.24(PGND) U18.25(PGND) U18.26(PGND) U18.27(NC) U18.28(NC) U18.29(NC) U18.30(NC) U18.31(DAP) U19.12(NC) U19.13(NC) U19.14(NC) U19.15(NC) U19.17(SYNC/MODE) U19.19(AGND) U19.23(PGND) U19.24(PGND) U19.25(PGND) U19.26(PGND) U19.27(NC) U19.28(NC) U19.29(NC) U19.30(NC) U19.31(DAP) U20.12(NC) U20.13(NC) U20.14(NC) U20.15(NC) U20.17(SYNC/MODE) U20.19(AGND) U20.23(PGND) U20.24(PGND) U20.25(PGND) U20.26(PGND) U20.27(NC) U20.28(NC) U20.29(NC) U20.30(NC) U20.31(DAP) U21.12(NC) U21.13(NC) U21.14(NC) U21.15(NC) U21.17(SYNC/MODE) U21.19(AGND) U21.23(PGND) U21.24(PGND) U21.25(PGND) U21.26(PGND) U21.27(NC) U21.28(NC) U21.29(NC) U21.30(NC) U21.31(DAP) U22.12(NC) U22.13(NC) U22.14(NC) U22.15(NC) U22.19(AGND) U22.23(PGND) U22.24(PGND) U22.25(PGND) U22.26(PGND) U22.27(NC) U22.28(NC) U22.29(NC) U22.30(NC) U22.31(DAP)
1V2: C153.1 C154.1 C155.1(+) C156.1(+) J25.1 J25.2 J27.1 L2.2 R117.2 R118.2 TP66.1 TP67.1 ; off-sheet 1V2
1V2_MEM: C175.1 C176.1(+) C177.1(+) J31.1 J31.2 J33.1 L4.2 R127.2 R128.2 TP82.1 TP83.1 ; off-sheet 1V2_MEM
1V2_VCCO: C157.1 C158.1(+) C159.1(+) J26.1 J26.2 J28.1 L3.2 R119.2 R120.2 TP68.1 TP69.1 ; off-sheet 1V2_VCCO
2V5_DDR: C178.1 C179.1(+) C180.1(+) J32.1 J32.2 J34.1 L5.2 R129.2 R130.2 TP80.1 TP81.1 ; off-sheet 2V5_DDR
3V3_VCCO: C164.1 C165.1 C185.1 C186.1 C191.1 C192.1 C193.1(+) C196.1 J37.1 J37.2 J38.1 L6.2 R137.2 R138.2 TP94.1 TP95.1 U18.8(BIAS) U18.17(SYNC/MODE) U19.8(BIAS) U20.8(BIAS) U21.8(BIAS) U22.8(BIAS) ; off-sheet 3V3_VCCO
12V0_SYS: C147.1 C148.1 C149.1 C150.1 C151.1 C152.1 C168.1 C169.1 C170.1 C171.1 C172.1 C173.1 C174.1 C188.1 C189.1 C190.1 U18.20(PVIN) U18.21(PVIN) U18.22(PVIN) U19.20(PVIN) U19.21(PVIN) U19.22(PVIN) U20.20(PVIN) U20.21(PVIN) U20.22(PVIN) U21.20(PVIN) U21.21(PVIN) U21.22(PVIN) U22.20(PVIN) U22.21(PVIN) U22.22(PVIN) ; off-sheet 12V0_SYS
BOOT_1V2: C145.1 U18.6(CBOOT)
BOOT_1V2_MEM: C166.1 U20.6(CBOOT)
BOOT_1V2_VCCO: C146.1 U19.6(CBOOT)
BOOT_2V5_DDR: C167.1 U21.6(CBOOT)
BOOT_3V3_VCCO: C187.1 U22.6(CBOOT)
EN_1V2: U18.18(EN) ; off-sheet EN_1V2
EN_1V2_MEM: U20.18(EN) ; off-sheet EN_1V2_MEM
EN_1V2_VCCO: U19.18(EN) ; off-sheet EN_1V2_VCCO
EN_2V5_DDR: U21.18(EN) ; off-sheet EN_2V5_DDR
EN_3V3_VCCO: U22.18(EN) ; off-sheet EN_3V3_VCCO
FB_1V2: C162.2 R121.1 R125.2 U18.11(FB)
FB_1V2_MEM: C183.2 R131.1 R135.2 U20.11(FB)
FB_1V2_VCCO: C163.2 R122.1 R126.2 U19.11(FB)
FB_2V5_DDR: C184.2 R132.1 R136.2 U21.11(FB)
FB_3V3_VCCO: C195.2 R139.1 R141.2 U22.11(FB)
PG_1V2: U18.16(PGOOD) ; off-sheet PG_1V2
PG_1V2_MEM: U20.16(PGOOD) ; off-sheet PG_1V2_MEM
PG_1V2_VCCO: U19.16(PGOOD) ; off-sheet PG_1V2_VCCO
PG_2V5_DDR: U21.16(PGOOD) ; off-sheet PG_2V5_DDR
PG_3V3_VCCO: U22.16(PGOOD) ; off-sheet PG_3V3_VCCO
RT_1V2: R123.2 U18.9(RT)
RT_1V2_MEM: R133.2 U20.9(RT)
RT_1V2_VCCO: R124.2 U19.9(RT)
RT_2V5_DDR: R134.2 U21.9(RT)
RT_3V3_VCCO: R140.2 U22.9(RT)
SW_1V2: C145.2 L2.1 TP71.1 U18.1(SW) U18.2(SW) U18.3(SW) U18.4(SW) U18.5(SW)
SW_1V2_MEM: C166.2 L4.1 TP84.1 U20.1(SW) U20.2(SW) U20.3(SW) U20.4(SW) U20.5(SW)
SW_1V2_VCCO: C146.2 L3.1 TP70.1 U19.1(SW) U19.2(SW) U19.3(SW) U19.4(SW) U19.5(SW)
SW_2V5_DDR: C167.2 L5.1 TP85.1 U21.1(SW) U21.2(SW) U21.3(SW) U21.4(SW) U21.5(SW)
SW_3V3_VCCO: C187.2 L6.1 TP96.1 U22.1(SW) U22.2(SW) U22.3(SW) U22.4(SW) U22.5(SW)
VCC_1V2: C160.1 U18.7(VCC)
VCC_1V2_MEM: C181.1 U20.7(VCC)
VCC_1V2_VCCO: C161.1 U19.7(VCC)
VCC_2V5_DDR: C182.1 U21.7(VCC)
VCC_3V3_VCCO: C194.1 U22.7(VCC) U22.17(SYNC/MODE) ; off-sheet VCC_3V3_VCCO
NetC162_1: C162.1 R117.1 R118.1 R121.2 TP72.1
NetC163_1: C163.1 R119.1 R120.1 R122.2 TP73.1
NetC183_1: C183.1 R127.1 R128.1 R131.2 TP86.1
NetC184_1: C184.1 R129.1 R130.1 R132.2 TP87.1
NetC195_1: C195.1 R137.1 R138.1 R139.2 TP97.1

Not connected (* = marked no-connect by the designer): U18 10(SS/TRK); U19 10(SS/TRK); U20 10(SS/TRK); U21 10(SS/TRK); U22 10(SS/TRK)

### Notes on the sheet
- Buck Rails
- 1V2 @ 2A
  VGTY_AVTT, VGTY_AVTTRCAL
- 6
- 1V2_VCCO @ 4A
  VCCO (7xx XPIO)
- 1
- (Remote)
- (near R118) (Local)
- (near R120) (Local)
- (near U19) (Auto)
- (near R123) (1MHz)
- (PWM)
- (near R124) (1MHz)
- 1V2_MEM @ 6A
  VDDQ, 3302  VLDOIN
- 2V5_DDR @ 3A
  DDR, 1111 inputs (for 1V5_GTY, 1V5, & 0V92)
- (near R128) (Local)
- (near R130) (Local)
- (near U20) (Auto)
- (near R133) (1MHz)
- (near R134) (1MHz)
- (near U21) (Auto)
- 3V3_VCCO @ 6A
  VCCO (302 HDIO, 50x PSIO), 73801_IN, 1111_BIAS, 3302_VDD
- (near R137) (Remote)
- (near R138) (Local)
- (near R140) (1MHz)

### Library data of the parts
C145 C146 C166 C167 C187 = CMP-0007695-2: as C140 on sheet TIDA-050088_LDOs
C147 C148 C150 C151 C168 C169 C171-C173 C188 C189 = CMP-0064938-2: as C139 on sheet TIDA-050088_LDOs
C149 C152 C170 C174 C190 = CMP-0007695-2: CAP CER 0.47UF 25V X7R 0805; Manufacturer: Kemet; Polarized: N; Cap_Case: 0805
C153 C154 C157 C175 C178 C191 C192 = CMP-0009154-2: as C141 on sheet TIDA-050088_LDOs
C155 C156 C158 C159 C176 C177 C179 C180 C193 = CMP-0011556-2: as C143 on sheet TIDA-050088_LDOs
C160 C161 C181 C182 C194 = CMP-0007867-2: CAP, CERM, 2.2 uF, 16 V, +/- 10%, X7R, 0805; Manufacturer: TDK; TaMin_C: -55°C; ESR_ohm: 4.9m; Polarized: N; SizeAreaWB_mm2: 6.75; Value1: 0.0049 ohm; U/M: EA; Value: 2.2uF; TaMax_C: 125°C; SizeZ_mm: 1.45; SizeX_mm: 2; SizeY_mm: 1.25; Cap_Case: 0805; SizeArea_mm2: 2.5; AEC Category: Q200
C162 C163 C183 C184 = CMP-0007211-4: CAP, CERM, 36 pF, 50 V, +/- 5%, C0G/NP0, 0603; Manufacturer: MuRata; TaMin_C: -55°C; Polarized: N; SizeAreaWB_mm2: 4.68; Value1: Unknown; U/M: EA; Value: 36pF; TaMax_C: 125°C; SizeZ_mm: 1; SizeX_mm: 1.6; SizeY_mm: 0.8; SizeArea_mm2: 1.28; AEC Category: Q200
C164 C165 C185 C186 C196 = CMP-0007729-2: CAP, CERM, 1 uF, 16 V, +/- 10%, X7R, 0805; Manufacturer: Kemet; TaMin_C: -55°C; ESR_ohm: 15m; Polarized: N; SizeAreaWB_mm2: 6.75; Value1: 0.015 ohm; U/M: EA; Value: 1uF; TaMax_C: 125°C; SizeZ_mm: 1.45; SizeX_mm: 2; SizeY_mm: 1.25; Cap_Case: 0805; SizeArea_mm2: 2.5; IRMS_A: 8.19A; AEC Category: Q200
C195 = CMP-0007171-4: CAP, CERM, 100 pF, 50 V, +/- 5%, C0G/NP0, 0603; Manufacturer: MuRata; TaMin_C: -55°C; Polarized: N; SizeAreaWB_mm2: 4.68; Value1: Unknown; U/M: EA; Value: 100pF; TaMax_C: 125°C; SizeZ_mm: 1; SizeX_mm: 1.6; SizeY_mm: 0.8; SizeArea_mm2: 1.28; AEC Category: Q200
J25 J26 J31 J32 J37 = CMP-0055393-3: as J8-J10 on sheet TIDA-050088_LDOs
J27 J28 J33 J34 J38 = CMP-0098472-1: as J11-J13 on sheet TIDA-050088_LDOs
J29 J30 J35 J36 J39 = CMP-0055389-3: as J14-J16 on sheet TIDA-050088_LDOs
L2-L4 = CMP-0061006-2: Inductor, Shielded, Composite, 800 nH, 13 A, 0.01 ohm, AEC-Q200 Grade 1, SMD; Manufacturer: Coilcraft; Isat: 18.5A @ 30% inductance drop; Irms: 13A @ 40C rise; Green_Lifecycle: Not Set; SizeAreaWB_mm2: 54.4544; DCR_ohm: 10m; Green_REACh: Incomplete; Value: 800nH; Imax_A: 13A; SizeZ_mm: 3.1; SizeX_mm: 5.28; SizeY_mm: 5.48; SizeArea_mm2: 28.9344; AEC Qualified: 1; AEC Category: Q200; AEC Grade: Y
L5 = CMP-0060999-2: Inductor, Shielded, Composite, 1.2 µH, 11.1 A, 0.01 ohm, AEC-Q200 Grade 1, SMD; Manufacturer: Coilcraft; Isat: 12.5A @ 30% inductance drop; Irms: 11.1A @ 40C rise; Green_Lifecycle: Not Set; SizeAreaWB_mm2: 54.4544; DCR_ohm: 10m; Green_REACh: Incomplete; Value: 1.2uH; Imax_A: 11.1A; SizeZ_mm: 3.1; SizeX_mm: 5.28; SizeY_mm: 5.48; SizeArea_mm2: 28.9344; Ind_H: 1.2µH; AEC Qualified: 1; AEC Category: Q200; AEC Grade: Y
L6 = CMP-0061014-2: Inductor, Shielded, Composite, 1.8 µH, 14 A, 0.01052 ohm, AEC-Q200 Grade 1, SMD; Manufacturer: Coilcraft; Value: 1.8uH; AEC Grade: 1; SizeX_mm: 6.36; AEC Category: Q200; Green_REACh: Incomplete; Value2: 14A; SizeArea_mm2: 41.7216; SizeZ_mm: 3.1; SizeAreaWB_mm2: 71.5616; AEC Qualified: Y; Isat: 18.2A @ 30% inductance drop; SizeY_mm: 6.56; DCR_ohm: 10.52m; Irms: 14A @ 40C rise; Green_Lifecycle: Not Set
R117-R120 R127-R130 R137 R138 = CMP-0023387-3: as R98 on sheet TIDA-050088_LDOs
R121 R122 R131 R132 = CMP-0024307-2: RES 50.5K OHM 0.1% 0.21W 0603; Manufacturer: Vishay Dale; Value_Code: 50k5
R123 R124 R133 R134 R140 = CMP-0022364-4: RES, 38.3 k, 1%, 0.1 W, AEC-Q200 Grade 0, 0603; Manufacturer: Vishay-Dale; Power_W: 100mW; TempCo: 100 ppm/C; Value_Code: 38k3; Value: 38.3k; EIA_Code: E96; SizeX_mm: 1.6; SizeY_mm: 0.8; SizeZ_mm: 1; Value2: 0.1W; SizeArea_mm2: 1.28; AEC Qualified: Y; VDC_V: 75V; AEC Category: Q200; AEC Grade: 0
R125 R126 R135 = CMP-0024010-3: RES SMD 261K OHM 0.1% 1/10W 0603; Manufacturer: Panasonic Electronic Components
R136 = CMP-0024127-2: RES 34K OHM 0.1% 1/10W 0603; Manufacturer: KOA Speer Electronics, Inc.
R139 = CMP-0024307-2: RES 50K OHM 0.1% 1/10W 0603; Manufacturer: Yageo
R141 = CMP-0023960-3: RES, 22.1 k, 0.1%, 0.1 W, 0603; Manufacturer: Yageo America; Power_W: 100mW; TempCo: 25 ppm/C; Value_Code: 22k1; U/M: EA; Value: 22.1k; EIA_Code: E192; SizeX_mm: 1.6; SizeY_mm: 0.8; SizeZ_mm: 1; Value2: 0.1W; SizeArea_mm2: 1.28; VDC_V: 75V; AEC Category: Q200
TP66-TP69 TP80-TP83 TP94 TP95 = CMP-0055147-2: as TP33-TP37 on sheet TIDA-050088_LDOs
TP70-TP73 TP84-TP87 TP96 TP97 = CMP-0055149-2: as TP38 on sheet TIDA-050088_LDOs
TP74-TP79 TP88-TP93 TP98-TP100 = CMP-0055148-2: as TP40-TP46 on sheet TIDA-050088_LDOs
U18-U22 = CMP-0091443-1: Radiation Hardened 3.5-V to 32-V, 6-A Synchronous Step-Down Voltage Converter in Space Enhanced Plastic, WQFN30; Manufacturer: Texas Instruments; Min Supply Voltage: 3.5V; Output Type: AdjustableProgrammable; Output Voltage: 1-30.4V; Switching Frequency: 350-2200kHz; Switching Topology: Buck; Nominal Supply Current: 0.6uA; SizeZ_mm: 0.8mm; Max Supply Voltage: 32V; Standoff Height: 0mm; AEC Qualified: No; Number Of Outputs: 1; TJmax_C: +125°C

## Sheet TIDA-050088_Aux.SchDoc
size 558 x 431 mm; Date: Not shown in title block; ApprovedBy: Not shown in title block; CheckedBy: Not shown in title block; Author: Not shown in title block; CompanyName: Not shown in title block; Engineer: Not shown in title block; Organization: Not shown in title block; Address1: Not shown in title block; Address2: Not shown in title block; Address3: Not shown in title block; Address4: Not shown in title block; DocumentNumber: 2; Revision: Use project parameter SCH_Rev; SheetNumber: 6; SheetTotal: 7; PageSetup: Record=PageOptions¦CenterHorizontal=True¦CenterVertical=True¦PrintScale=1.00¦XCorrection=1.00¦YCorrection=1.00¦PrintKind=0¦BorderSize=5000000¦LeftOffset=0¦BottomOffset=0¦Orientation=2¦PaperLength=1000¦PaperWidth=1000¦Scale=100¦PaperSource=15¦PrintQuality=600¦MediaType=1¦DitherType=10¦PaperKind=Letter¦PrintScaleMode=1
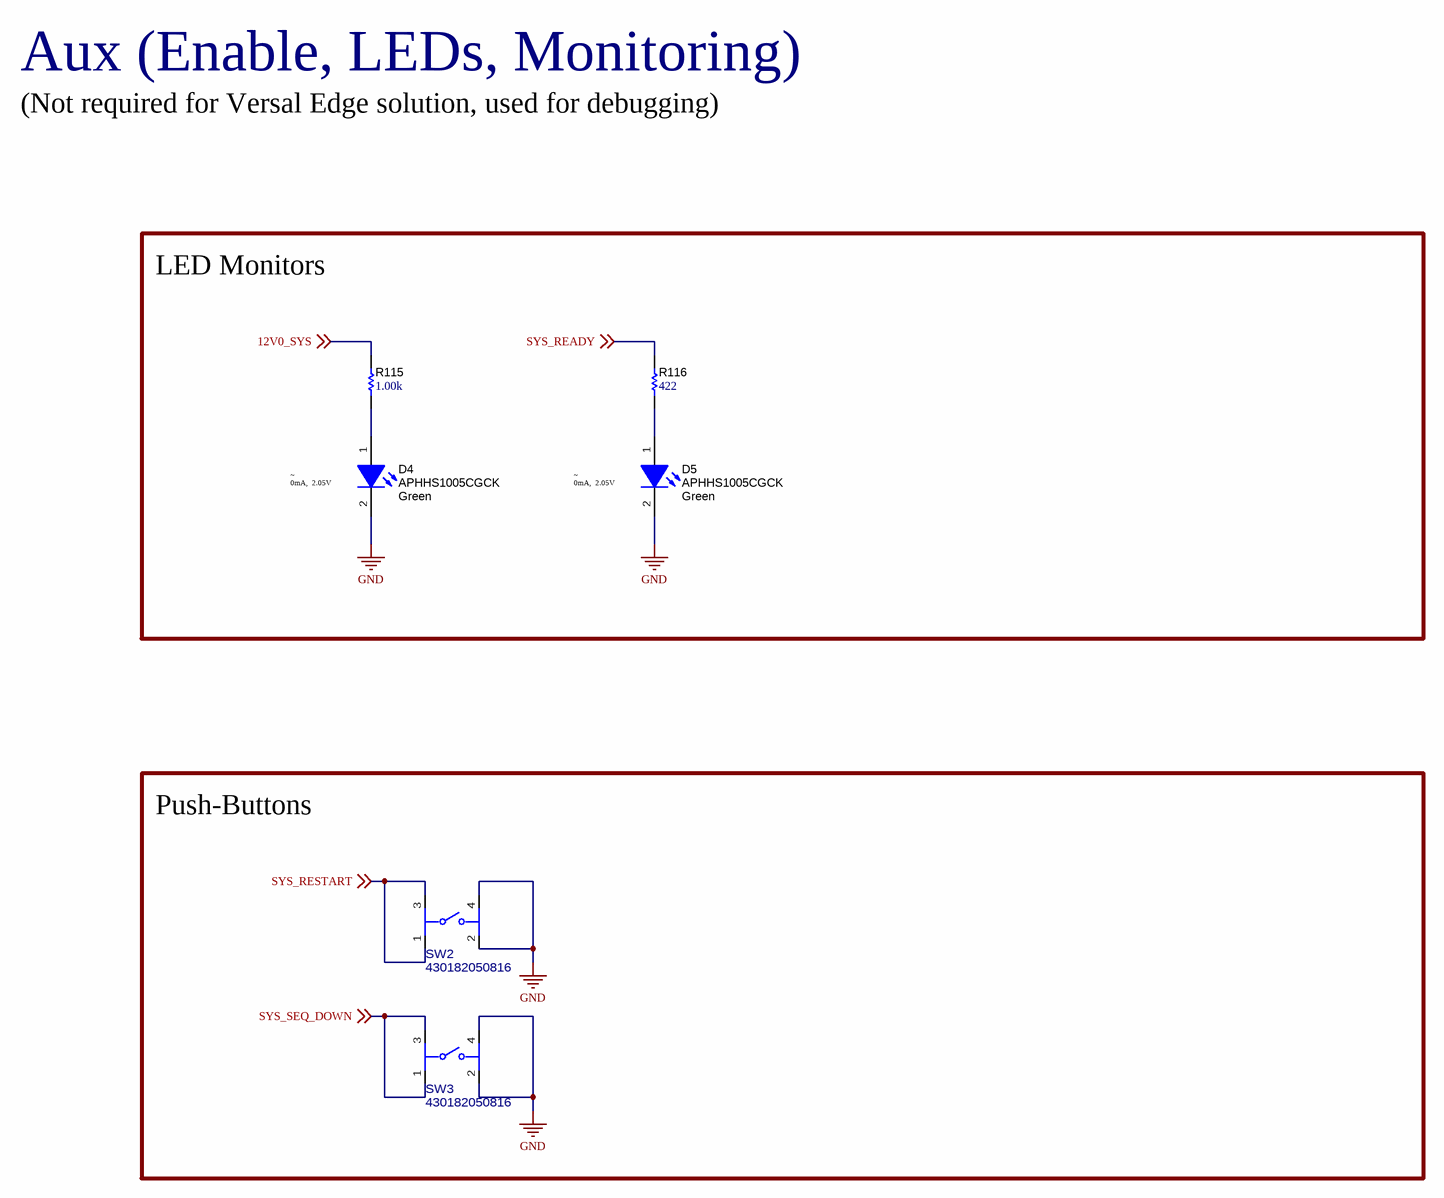
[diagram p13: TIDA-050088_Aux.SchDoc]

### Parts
D4  APHHS1005CGCK  value Green  [APHHS1005_Green]
D5  APHHS1005CGCK  value Green  [APHHS1005_Green]
R115  ValueDisplayed: 1.00k  [0805_HV]  (hidden comment: ERJ-6ENF1001V)
R116  ValueDisplayed: 422  [0805_HV]  (hidden comment: CRCW0805422RFKEA)
SW2  430182050816  [FP-430182050816_SMT_SW_6MM2_6MM2-MFG]
SW3  430182050816  [FP-430182050816_SMT_SW_6MM2_6MM2-MFG]

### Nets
GND: D4.2(K) D5.2(K) SW2.2 SW2.4 SW3.2 SW3.4
12V0_SYS: R115.2 ; off-sheet 12V0_SYS
SYS_READY: R116.2 ; off-sheet SYS_READY
SYS_RESTART: SW2.1 SW2.3 ; off-sheet SYS_RESTART
SYS_SEQ_DOWN: SW3.1 SW3.3 ; off-sheet SYS_SEQ_DOWN
NetD4_1: D4.1(A) R115.1
NetD5_1: D5.1(A) R116.1

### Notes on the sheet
- Aux (Enable, LEDs, Monitoring)
- (Not required for Versal Edge solution, used for debugging)
- LED Monitors
- (near D4) ~
  0mA,  2.05V
- (near D5) ~
  0mA,  2.05V
- Push-Buttons

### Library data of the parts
D4 D5 = CMP-0067682-2: LED, Green, SMD; Manufacturer: Kingbright; Value1: 0.075W; Vf_V: 2.1V; Vr_V: 5V; SizeArea_mm2: 0.5; Power_TotalModule: 75mW; Tjmax_C: 85°C; Angle: 120.0; SizeAreaWB_mm2: 3.0; SizeX_mm: 1.0; Ir_A: 10µA; Io_A: 20mA; SizeZ_mm: 0.6
R115 = CMP-0021519-3: RES, 1.00 k, 1%, 0.125 W, AEC-Q200 Grade 0, 0805; Manufacturer: Panasonic; Power_W: 125mW; TempCo: 100 ppm/C; Value_Code: 1k00; Value: 1.00k; EIA_Code: E96; Res_ohm: 1k; SizeX_mm: 2; SizeY_mm: 1.25; SizeZ_mm: 1.45; Value2: 0.125W; SizeArea_mm2: 2.5; AEC Qualified: Y; AEC Category: Q200; AEC Grade: 0; SizeAreaWB_mm2: 6.75
R116 = CMP-0021253-3: RES, 422, 1%, 0.125 W, AEC-Q200 Grade 0, 0805; Manufacturer: Vishay-Dale; Power_W: 125mW; TempCo: 100 ppm/C; Value_Code: 422R; Value: 422; EIA_Code: E96; SizeX_mm: 2; SizeY_mm: 1.25; SizeZ_mm: 1.45; Value2: 0.125W; SizeArea_mm2: 2.5; AEC Qualified: Y; VDC_V: 150V; AEC Category: Q200; AEC Grade: 0
SW2 SW3 = CMP-0097324-1: Switch Tactile N.O. SPST Round Button Gull Wing 0.05A 12VDC 1000000Cycles 1.57N SMD Reel; Manufacturer: Wurth Electronics; AEC Qualified: No; Operating Force: 160gf; Coil Resistance_ohm: 100mΩ; VDC_V: 12V; Circuit: SPST-NO; SizeZ_mm: 5.15mm; Contact Current Rating: 50mA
